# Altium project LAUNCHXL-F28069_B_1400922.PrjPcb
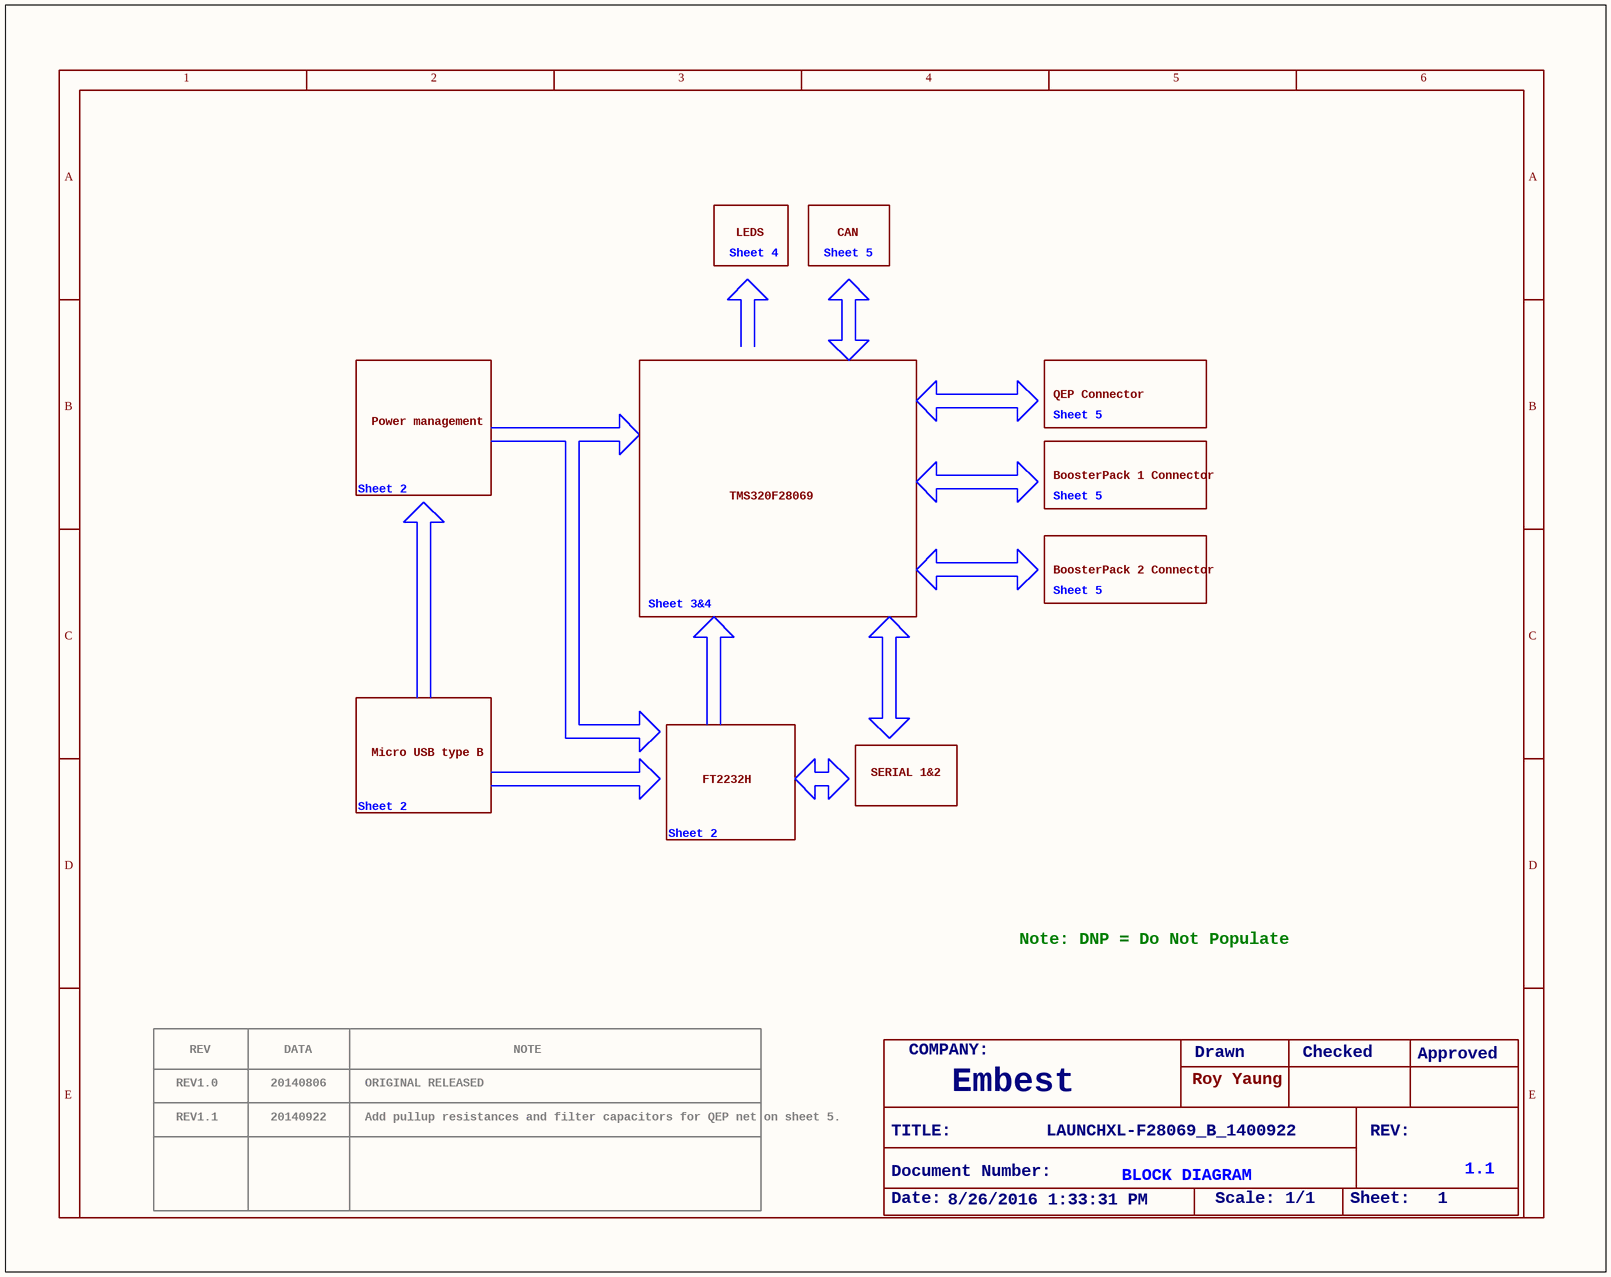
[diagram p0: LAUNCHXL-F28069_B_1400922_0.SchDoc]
7 sheets, 199 parts. Net scope: global (net labels, ports and power ports of the same name join across sheets).
Board file: LAUNCHXL-F28069_B_1400922.PcbDoc
Sheets:
  LAUNCHXL-F28069_B_1400922_0.SchDoc
  LAUNCHXL-F28069_B_1400922_1.SchDoc
  LAUNCHXL-F28069_B_1400922_2.SchDoc
  LAUNCHXL-F28069_B_1400922_3.SchDoc
  LAUNCHXL-F28069_B_1400922_4.SchDoc
  LAUNCHXL-F28069_B_1400922_5.SchDoc
  LAUNCHXL-F28069_B_1400922_6.SchDoc

## Sheet LAUNCHXL-F28069_B_1400922_0.SchDoc: LAUNCHXL-F28069_B_1400922
size 301 x 238 mm; Date: 8/26/2016 1:33:31 PM; SheetNumber: 1

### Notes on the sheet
- Sheet 4
- LEDS
- Sheet 5
- CAN
- QEP Connector
- Power management
- BoosterPack 1 Connector
- Sheet 2
- TMS320F28069
- Sheet 3&4
- BoosterPack 2 Connector
- Micro USB type B
- FT2232H
- SERIAL 1&2
- Note: DNP = Do Not Populate
- REV1.0
- REV
- 20140806
- DATA
- ORIGINAL RELEASED
- NOTE
- COMPANY:
- Embest
- Roy Yaung
- Drawn
- Checked
- Approved
- REV1.1
- 20140922
- Add pullup resistances and filter capacitors for QEP net on sheet 5.
- TITLE:
- LAUNCHXL-F28069_B_1400922
- REV:
- Date:
- Document Number:
- 8/26/2016 1:33:31 PM
- BLOCK DIAGRAM
- Scale: 1/1
- Sheet:
- 1
- 1.1

## Sheet LAUNCHXL-F28069_B_1400922_1.SchDoc: LAUNCHXL-F28069_B_1400922
size 301 x 237 mm; Date: 8/26/2016 1:33:31 PM; SheetNumber: 2
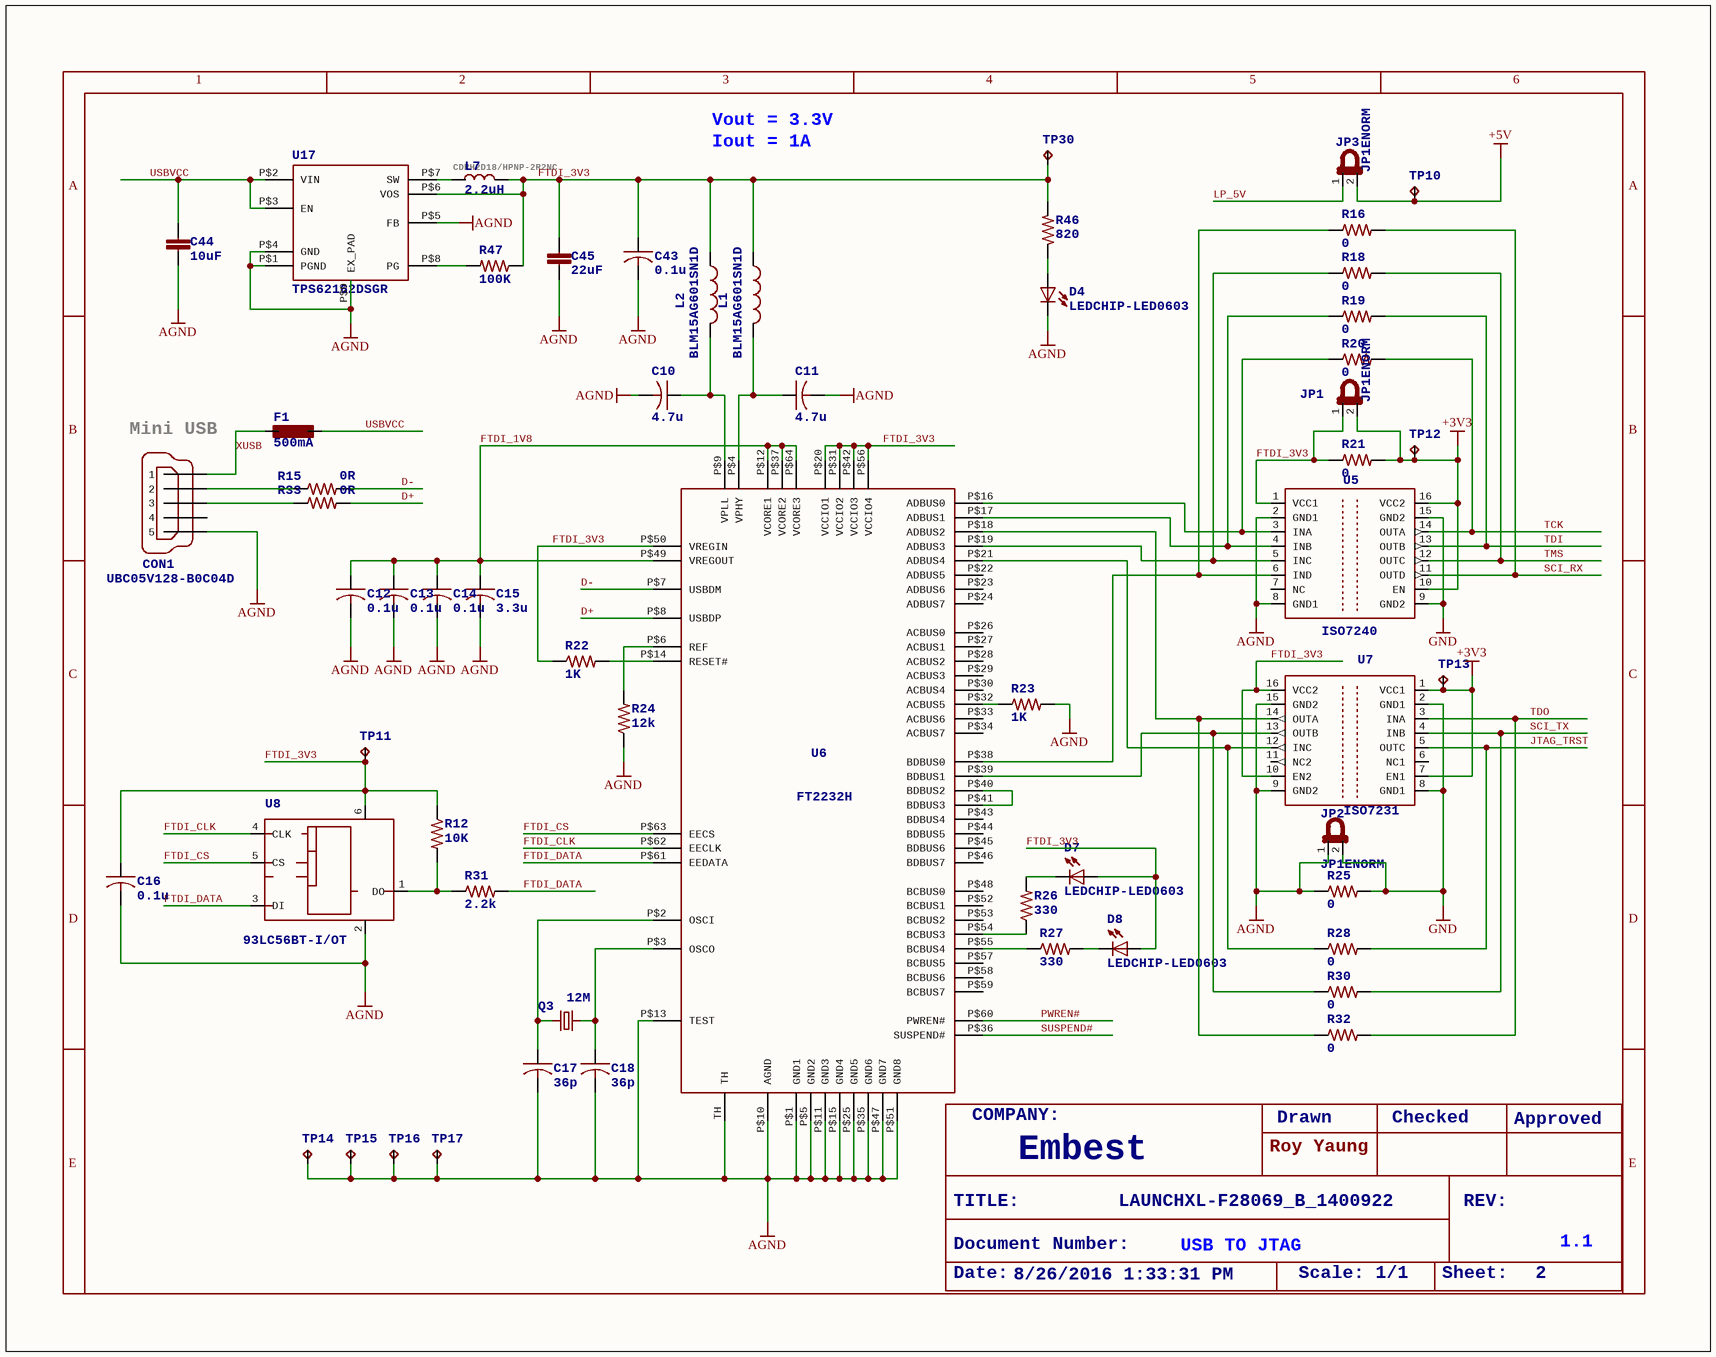
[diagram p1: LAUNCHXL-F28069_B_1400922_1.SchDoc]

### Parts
C10  4.7u  [C0402]
C11  4.7u  [C0402]
C12  0.1u  [C0402]
C13  0.1u  [C0402]
C14  0.1u  [C0402]
C15  3.3u  [C0402]
C16  0.1u  [C0402]
C17  36p  [C0402]
C18  36p  [C0402]
C43  0.1u  [C0402]
C44  10uF  [SPARKFUN_1210]
C45  22uF  [SPARKFUN_1210]
CON1  UBC05V128-B0C04D  [32005-201]
D4  LEDCHIP-LED0603  [CHIP-LED0603]
D7  LEDCHIP-LED0603  [CHIP-LED0603]
D8  LEDCHIP-LED0603  [CHIP-LED0603]
F1  500mA  [L1812]
JP1  JP1ENORM  [JP1]
JP2  JP1ENORM  [JP1]
JP3  JP1ENORM  [JP1]
L1  BLM15AG601SN1D  [R0402]
L2  BLM15AG601SN1D  [R0402]
L7  2.2uH  [INDUCT-3.2*3.2]
Q3  12M  [HC49UP]
R12  10K  [R0402]
R15  0R  [R0402]
R16  0  [R1206]
R18  0  [R1206]
R19  0  [R1206]
R20  0  [R1206]
R21  0  [R1206]
R22  1K  [R0402]
R23  1K  [R0402]
R24  12k  [R0402]
R25  0  [R1206]
R26  330  [R0402]
R27  330  [R0402]
R28  0  [R1206]
R30  0  [R1206]
R31  2.2k  [R0402]
R32  0  [R1206]
R33  0R  [R0402]
R46  820  [R0402]
R47  100K  [R0402]
TP10  TESTPAD_TPB1,27  [TESTPAD_B1,27]  (value not drawn)
TP11  TESTPAD_TPB1,27  [TESTPAD_B1,27]  (value not drawn)
TP12  TESTPAD_TPB1,27  [TESTPAD_B1,27]  (value not drawn)
TP13  TESTPAD_TPB1,27  [TESTPAD_B1,27]  (value not drawn)
TP14  TESTPAD_TPB1,27  [TESTPAD_B1,27]  (value not drawn)
TP15  TESTPAD_TPB1,27  [TESTPAD_B1,27]  (value not drawn)
TP16  TESTPAD_TPB1,27  [TESTPAD_B1,27]  (value not drawn)
TP17  TESTPAD_TPB1,27  [TESTPAD_B1,27]  (value not drawn)
TP30  TESTPAD_TPB1,27  [TESTPAD_B1,27]  (value not drawn)
U5  ISO7240  [SO-16DW]
U6  FT2232H  [QFN64]
U7  ISO7231  [SO-16DW]
U8  93LC56BT-I/OT  [SOT23-6]
U17  TPS62162DSGR  [TI_DSG8]
U$9  ROY_JUMPER  [ROY_JUMPER]  (value not drawn)
U$10  ROY_JUMPER  [ROY_JUMPER]  (value not drawn)
U$11  ROY_JUMPER  [ROY_JUMPER]  (value not drawn)

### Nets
+3V3: JP1.2 R21.2 TP12.TP TP13.TP U5.10(EN) U5.16(VCC2) U7.1(VCC1) U7.7(EN1)
+5V: JP3.2 TP10.TP  [project net EQEP1A]
AGND: C10.2 C11.2 C12.2 C13.2 C14.2 C15.2 C16.2 C17.2 C18.2 C43.2 C44.1 C45.1 CON1.5 D4.C JP2.1 R23.2 R24.1 R25.1 TP14.TP TP15.TP TP16.TP TP17.TP U5.2(GND1) U5.8(GND1) U6.P$1(GND1) U6.P$5(GND2) U6.P$10(AGND) U6.P$11(GND3) U6.P$13(TEST) U6.P$15(GND4) U6.P$25(GND5) U6.P$35(GND6) U6.P$47(GND7) U6.P$51(GND8) U6.TH U7.9(GND2) U7.15(GND2) U8.2(GND) U17.P$1(PGND) U17.P$4(GND) U17.P$5(FB) U17.P$9(EX_PAD)
GND: JP2.2 R25.2 U5.9(GND2) U5.15(GND2) U7.2(GND1) U7.8(GND1)
D+: R33.2 U6.P$8(USBDP)
D-: R15.2 U6.P$7(USBDM)
FTDI_1V8: C12.1 C13.1 C14.1 C15.1 U6.P$12(VCORE1) U6.P$37(VCORE2) U6.P$49(VREGOUT) U6.P$64(VCORE3)
FTDI_3V3: C16.1 C43.1 C45.2 D7.A D8.A JP1.1 L1.1 L2.1 L7.P$1 R12.1 R21.1 R22.1 R46.2 R47.1 TP11.TP TP30.TP U5.1(VCC1) U6.P$20(VCCIO1) U6.P$31(VCCIO2) U6.P$42(VCCIO3) U6.P$50(VREGIN) U6.P$56(VCCIO4) U7.10(EN2) U7.16(VCC2) U8.6(VCC) U17.P$6(VOS)
FTDI_CLK: U6.P$62(EECLK) U8.4(CLK)
FTDI_CS: U6.P$63(EECS) U8.5(CS)
FTDI_DATA: R31.2 U6.P$61(EEDATA) U8.3(DI)
JTAG_TRST: R28.2 U7.5(OUTC)
LP_5V: JP3.1
PWREN#: U6.P$60(PWREN#)
SCI_RX: R16.2 U5.11(OUTD)
SCI_TX: R30.2 U7.4(INB)
SUSPEND#: U6.P$36(SUSPEND#)
TCK: R20.2 U5.14(OUTA)
TDI: R19.2 U5.13(OUTB)
TDO: R32.2 U7.3(INA)
TMS: R18.2 U5.12(OUTC)
USBVCC: C44.2 F1.1 U17.P$2(VIN) U17.P$3(EN)
XUSB: CON1.1 F1.2
NetC10_1: C10.1 L2.2 U6.P$9(VPLL)
NetC11_1: C11.1 L1.2 U6.P$4(VPHY)
NetC17_1: C17.1 Q3.1 U6.P$2(OSCI)
NetC18_1: C18.1 Q3.2 U6.P$3(OSCO)
NetCON1_2: CON1.2 R15.1
NetCON1_3: CON1.3 R33.1
NetD4_A: D4.A R46.1
NetD7_C: D7.C R26.2
NetD8_C: D8.C R27.2
NetL7_P$2: L7.P$2 U17.P$7(SW)
NetR12_2: R12.2 R31.1 U8.1(DO)
NetR16_1: R16.1 U5.6(IND) U6.P$38(BDBUS0)
NetR18_1: R18.1 U5.5(INC) U6.P$19(ADBUS3)
NetR19_1: R19.1 U5.4(INB) U6.P$17(ADBUS1)
NetR20_1: R20.1 U5.3(INA) U6.P$16(ADBUS0)
NetR22_2: R22.2 U6.P$14(RESET#)
NetR23_1: R23.1 U6.P$32(ACBUS5)
NetR24_2: R24.2 U6.P$6(REF)
NetR26_1: R26.1 U6.P$54(BCBUS3)
NetR27_1: R27.1 U6.P$55(BCBUS4)
NetR28_1: R28.1 U6.P$21(ADBUS4) U7.12(INC)
NetR30_1: R30.1 U6.P$39(BDBUS1) U7.13(OUTB)
NetR32_1: R32.1 U6.P$18(ADBUS2) U7.14(OUTA)
NetR47_2: R47.2 U17.P$8(PG)
NetU6_P$40: U6.P$40(BDBUS2) U6.P$41(BDBUS3)

Not connected (* = marked no-connect by the designer): CON1 4; U5 7(NC); U6 P$22(ADBUS5) P$23(ADBUS6) P$24(ADBUS7) P$26(ACBUS0) P$27(ACBUS1) P$28(ACBUS2) P$29(ACBUS3) P$30(ACBUS4) P$33(ACBUS6) P$34(ACBUS7) P$43(BDBUS4) P$44(BDBUS5) P$45(BDBUS6) P$46(BDBUS7) P$48(BCBUS0) P$52(BCBUS1) P$53(BCBUS2) P$57(BCBUS5) P$58(BCBUS6) P$59(BCBUS7); U7 6(NC1) 11(NC2)

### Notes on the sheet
- Vout = 3.3V
- Iout = 1A
- (near L7) CDRH2D18/HPNP-2R2NC
- (near CON1) Mini USB
- (near U6) COMPANY:
- Embest
- Roy Yaung
- Drawn
- Checked
- Approved
- TITLE:
- LAUNCHXL-F28069_B_1400922
- REV:
- Date:
- Document Number:
- 8/26/2016 1:33:31 PM
- USB TO JTAG
- Scale: 1/1
- Sheet:
- 2
- 1.1

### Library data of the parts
C10-C18 C43 = C-USC0402: CAPACITOR, American symbol
C44 C45 = SPARKFUN_CAP1210: CapacitorStandard 0603 ceramic capacitor, and 0.1" leaded capacitor.
CON1 = MINI-USB-32005-201: MINI USB-B Conector   Source: www.cypressindustries.com
D4 D7 D8 = LEDCHIP-LED0603: LED   OSRAM: - CHIPLED LG R971, LG N971, LY N971, LG Q971, LY Q971, LO R971, LY R971 LH N974, LH R974 LS Q976, LO Q976, LY Q976 LO Q996 - Hyper CHIPLED LW Q18S LB Q993, LB Q99A, LB R99A - SideLED LS A670, LO A670, LY A670, LG A670, LP A670 LB A673, LV A673, LT A673, LW A673 LH A674 LY A675 LS A676, LA A676, LO A676, LY A676, LW A676 LS A679, LY A679, LG A679 -  Hyper Micro SIDELED® LS Y876, LA Y876, LO Y876, LY Y876 LT Y87S - SmartLED LW L88C, LW L88S LB L89C, LB L89S, LG L890 LS L89K, LO L89K, LY L89K LS L896, LA L896, LO L896, LY L896 - TOPLED LS T670, LO T670, LY T670, LG T670, LP T670 LSG T670, LSP T670, LSY T670, LOP T670, LYG T670 LG T671, LOG T671, LSG T671 LB T673, LV T673, LT T673, LW T673 LH T674 LS T676, LA T676, LO T676, LY T676, LB T676, LH T676, LSB T676, LW T676 LB T67C, LV T67C, LT T67C, LS T67K, LO T67K, LY T67K, LW E67C LS E67B, LA E67B, LO E67B, LY E67B, LB E67C, LV E67C, LT E67C LW T67C LS T679, LY T679, LG T679 LS T770, LO T770, LY T770, LG T770, LP T770 LB T773, LV T773, LT T773, LW T773 LH T774 LS E675, LA E675, LY E675, LS T675 LS T776, LA T776, LO T776, LY T776, LB T776 LHGB T686 LT T68C, LB T68C - Hyper Mini TOPLED® LB M676 - Mini TOPLED Santana® LG M470 LS M47K, LO M47K, LY M47K    Source: http://www.osram.convergy.de   LUXEON: - LUMILED® LXK2-PW12-R00, LXK2-PW12-S00, LXK2-PW14-U00, LXK2-PW14-V00 LXK2-PM12-R00, LXK2-PM12-S00, LXK2-PM14-U00 LXK2-PE12-Q00, LXK2-PE12-R00, LXK2-PE12-S00, LXK2-PE14-T00, LXK2-PE14-U00 LXK2-PB12-K00, LXK2-PB12-L00, LXK2-PB12-M00, LXK2-PB14-N00, LXK2-PB14-P00, LXK2-PB14-Q00 LXK2-PR12-L00, LXK2-PR12-M00, LXK2-PR14-Q00, LXK2-PR14-R00 LXK2-PD12-Q00, LXK2-PD12-R00, LXK2-PD12-S00 LXK2-PH12-R00, LXK2-PH12-S00 LXK2-PL12-P00, LXK2-PL12-Q00, LXK2-PL12-R00    Source: www.luxeon.com   KINGBRIGHT:   KA-3528ASYC Source: www.kingbright.com
F1 = L-EUL1812: INDUCTOR, European symbol
JP1-JP3 = JP1ENORM: JUMPER
L1 L2 = L-US0402: INDUCTOR, American symbol
L7 = VLF4012A`
Q3 = CRYSTALHC49UP: CRYSTAL
R12 R15 R22-R24 R26 R27 R31 R33 R46 R47 = R-US_R0402: RESISTOR, American symbol
R16 R18-R21 R25 R28 R30 R32 = R-US_R1206: RESISTOR, American symbol
TP10-TP17 TP30 = TESTPAD_TPB1,27: Test pad
U5 = ISO7240: HIGH SPEED QUAD DIGITAL ISOLATORS   Source: http://focus.ti.com/lit/ds/symlink/iso7240m.pdf
U8 = 93*: Serial EPROM   1 K/2 K/4 K, low voltage, Microwire

## Sheet LAUNCHXL-F28069_B_1400922_2.SchDoc: LAUNCHXL-F28069_B_1400922
size 301 x 237 mm; Date: 8/26/2016 1:33:33 PM; SheetNumber: 3
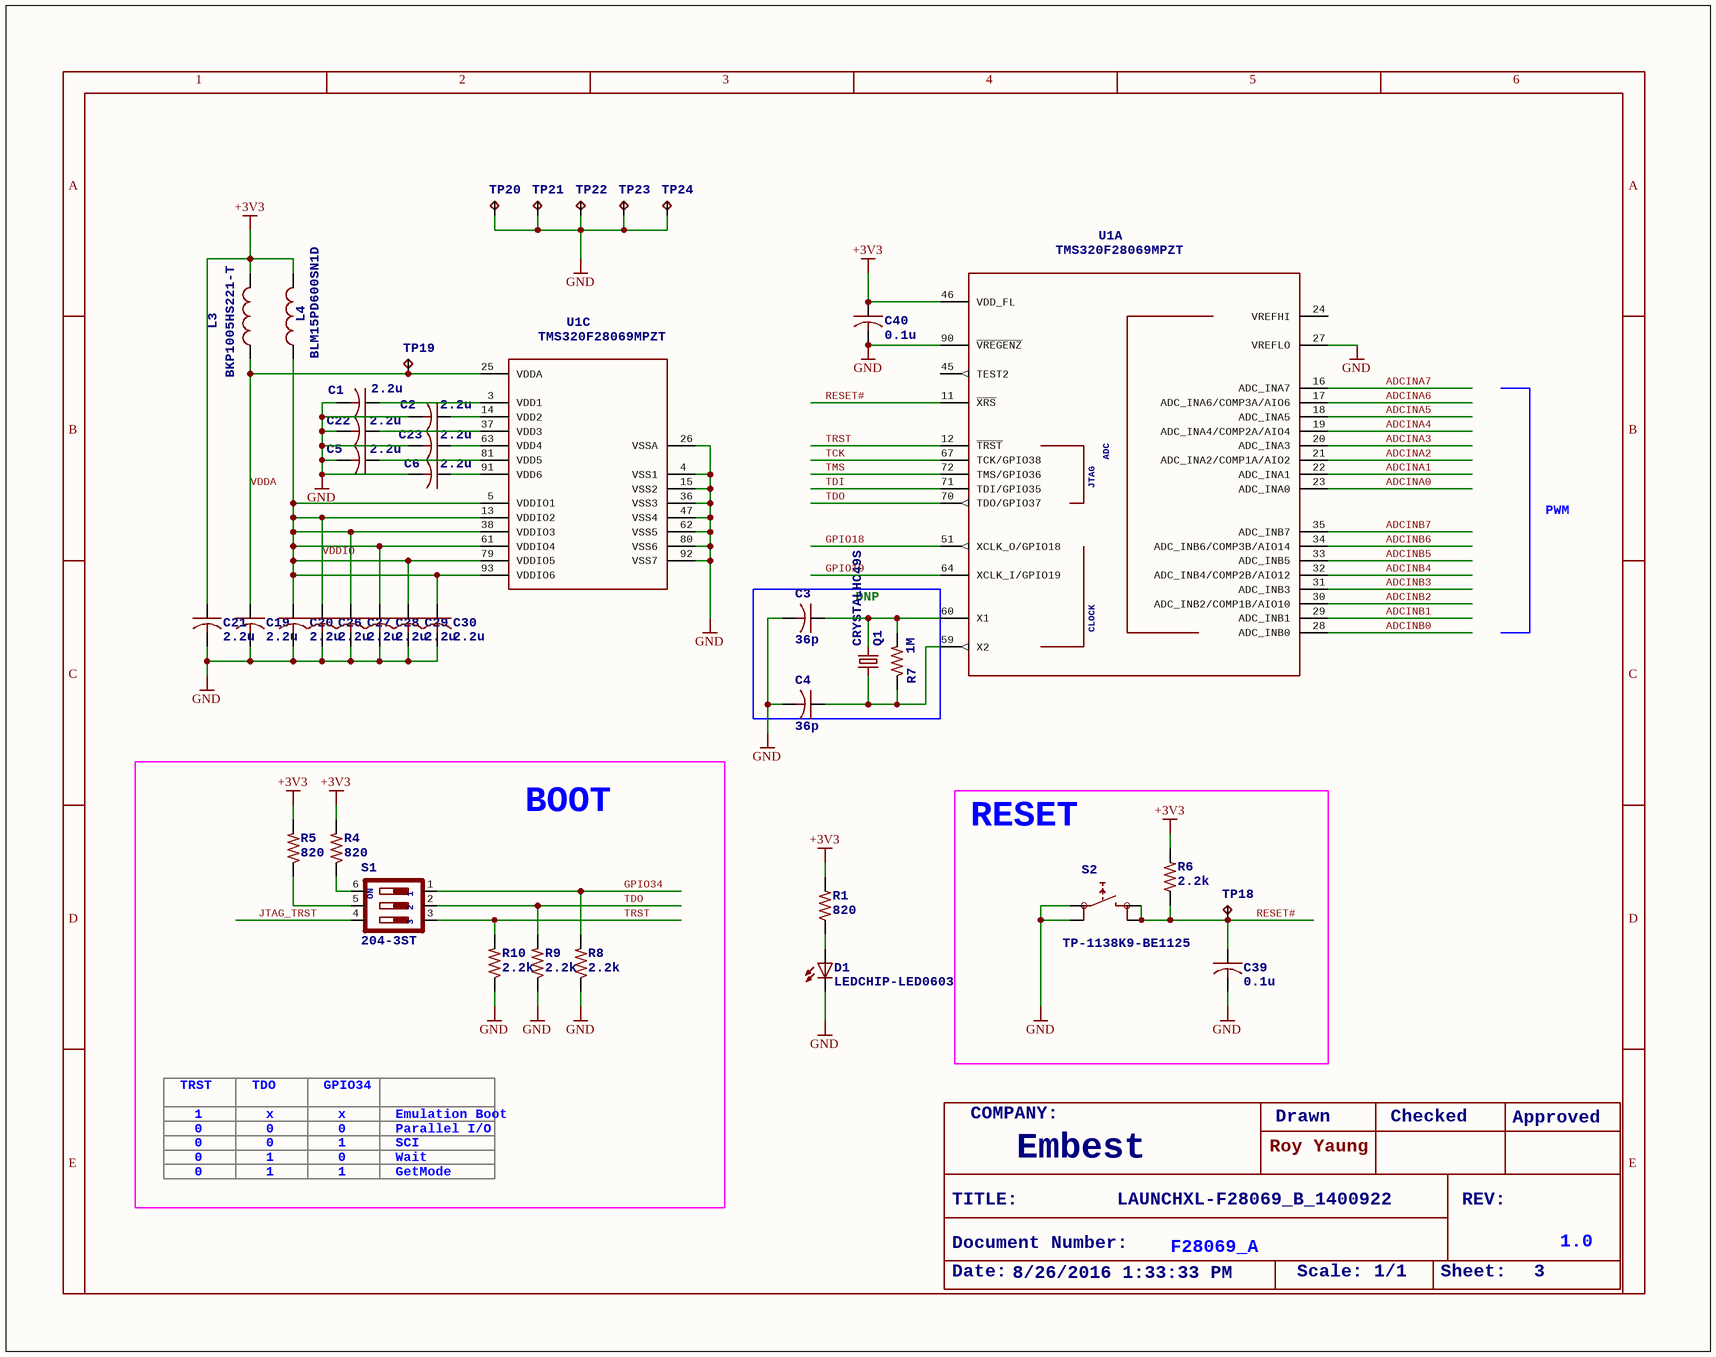
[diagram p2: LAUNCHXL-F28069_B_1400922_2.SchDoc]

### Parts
C1  2.2u  [C0402]
C2  2.2u  [C0402]
C3  36p  [C0402]
C4  36p  [C0402]
C5  2.2u  [C0402]
C6  2.2u  [C0402]
C19  2.2u  [C0402]
C20  2.2u  [C0402]
C21  2.2u  [C0402]
C22  2.2u  [C0402]
C23  2.2u  [C0402]
C26  2.2u  [C0402]
C27  2.2u  [C0402]
C28  2.2u  [C0402]
C29  2.2u  [C0402]
C30  2.2u  [C0402]
C39  0.1u  [C0402]
C40  0.1u  [C0402]
D1  LEDCHIP-LED0603  [CHIP-LED0603]
L3  BKP1005HS221-T  [R0402]
L4  BLM15PD600SN1D  [R0402]
Q1  CRYSTALHC49S  [HC49/S]
R1  820  [R0402]
R4  820  [R0402]
R5  820  [R0402]
R6  2.2k  [R0402]
R7  1M  [R0402]
R8  2.2k  [R0402]
R9  2.2k  [R0402]
R10  2.2k  [R0402]
S1  204-3ST  [CTS-219-03]
S2  TP-1138K9-BE1125  [FSMJSMA]
TP18  TESTPAD_TPB1,27  [TESTPAD_B1,27]  (value not drawn)
TP19  TESTPAD_TPB1,27  [TESTPAD_B1,27]  (value not drawn)
TP20  TESTPAD_TPB1,27  [TESTPAD_B1,27]  (value not drawn)
TP21  TESTPAD_TPB1,27  [TESTPAD_B1,27]  (value not drawn)
TP22  TESTPAD_TPB1,27  [TESTPAD_B1,27]  (value not drawn)
TP23  TESTPAD_TPB1,27  [TESTPAD_B1,27]  (value not drawn)
TP24  TESTPAD_TPB1,27  [TESTPAD_B1,27]  (value not drawn)
U1  TMS320F28069MPZT  [PQFP100]  (parts A,C of 3)

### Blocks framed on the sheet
DNP: C3 C4 Q1 R7
BOOT: R4 R5 R8-R10 S1
RESET: C39 R6 S2 TP18

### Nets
+3V3: C21.1 C40.1 L3.2 L4.2 R1.2 R4.2 R5.2 R6.2 U1.46(VDD_FL)
GND: C1.2 C2.2 C3.2 C4.2 C5.2 C6.2 C19.2 C20.2 C21.2 C22.2 C23.2 C26.2 C27.2 C28.2 C29.2 C30.2 C39.2 C40.2 D1.C R8.1 R9.1 R10.1 S2.P$1 S2.P$2 TP20.TP TP21.TP TP22.TP TP23.TP TP24.TP U1.4(VSS1) U1.15(VSS2) U1.26(VSSA) U1.27(VREFLO) U1.36(VSS3) U1.47(VSS4) U1.62(VSS5) U1.80(VSS6) U1.90(~{VREGENZ}) U1.92(VSS7)
ADCINA0: U1.23(ADC_INA0)
ADCINA1: U1.22(ADC_INA1)
ADCINA2: U1.21(ADC_INA2/COMP1A/AIO2)
ADCINA3: U1.20(ADC_INA3)
ADCINA4: U1.19(ADC_INA4/COMP2A/AIO4)
ADCINA5: U1.18(ADC_INA5)
ADCINA6: U1.17(ADC_INA6/COMP3A/AIO6)
ADCINA7: U1.16(ADC_INA7)
ADCINB0: U1.28(ADC_INB0)
ADCINB1: U1.29(ADC_INB1)
ADCINB2: U1.30(ADC_INB2/COMP1B/AIO10)
ADCINB3: U1.31(ADC_INB3)
ADCINB4: U1.32(ADC_INB4/COMP2B/AIO12)
ADCINB5: U1.33(ADC_INB5)
ADCINB6: U1.34(ADC_INB6/COMP3B/AIO14)
ADCINB7: U1.35(ADC_INB7)
GPIO18: U1.51(XCLK_O/GPIO18)
GPIO19: U1.64(XCLK_I/GPIO19)
GPIO34: R8.2 S1.1
JTAG_TRST: S1.4
RESET#: C39.1 R6.1 S2.P$3 S2.P$4 TP18.TP U1.11(~{XRS})
TCK: U1.67(TCK/GPIO38)
TDI: U1.71(TDI/GPIO35)
TDO: R9.2 S1.2 U1.70(TDO/GPIO37)
TMS: U1.72(TMS/GPIO36)
TRST: R10.2 S1.3 U1.12(~{TRST})
VDDA: C19.1 L3.1 TP19.TP U1.25(VDDA)
VDDIO: C20.1 C26.1 C27.1 C28.1 C29.1 C30.1 L4.1 U1.5(VDDIO1) U1.13(VDDIO2) U1.38(VDDIO3) U1.61(VDDIO4) U1.79(VDDIO5) U1.93(VDDIO6)
NetC1_1: C1.1 U1.3(VDD1)
NetC2_1: C2.1 U1.14(VDD2)
NetC3_1: C3.1 Q1.2 R7.2 U1.60(X1)
NetC4_1: C4.1 Q1.1 R7.1 U1.59(X2)
NetC5_1: C5.1 U1.81(VDD5)
NetC6_1: C6.1 U1.91(VDD6)
NetC22_1: C22.1 U1.37(VDD3)
NetC23_1: C23.1 U1.63(VDD4)
NetD1_A: D1.A R1.1
NetR4_1: R4.1 S1.6
NetR5_1: R5.1 S1.5

Not connected (* = marked no-connect by the designer): U1 24(VREFHI) 45(TEST2)

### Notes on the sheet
- PWM
- TRST
- TDO
- GPIO34
- 1
- 0
- x
- Emulation Boot
- Parallel I/O
- SCI
- Wait
- COMPANY:
- Embest
- Roy Yaung
- Drawn
- Checked
- Approved
- GetMode
- TITLE:
- LAUNCHXL-F28069_B_1400922
- REV:
- Date:
- Document Number:
- 8/26/2016 1:33:33 PM
- F28069_A
- Scale: 1/1
- Sheet:
- 3
- 1.0

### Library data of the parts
C1-C6 C19-C23 C26-C30 C39 C40 = C-USC0402: CAPACITOR, American symbol
D1 = LEDCHIP-LED0603: as D4 on sheet LAUNCHXL-F28069_B_1400922_1
L3 L4 = L-US0402: INDUCTOR, American symbol
Q1 = CRYSTALHC49S: CRYSTAL
R1 R4-R10 = R-US_R0402: RESISTOR, American symbol
S1 = 219-03*: Surface Mount DIP Switch Series 219 SMT   CTS Electronic Components Sourc: www.ctscorp.com
S2 = FSMJSMA
TP18-TP24 = TESTPAD_TPB1,27: Test pad
U1 = TMS320F28069PZSR

## Sheet LAUNCHXL-F28069_B_1400922_3.SchDoc: LAUNCHXL-F28069_B_1400922
size 301 x 237 mm; Date: 8/26/2016 1:33:34 PM; SheetNumber: 4
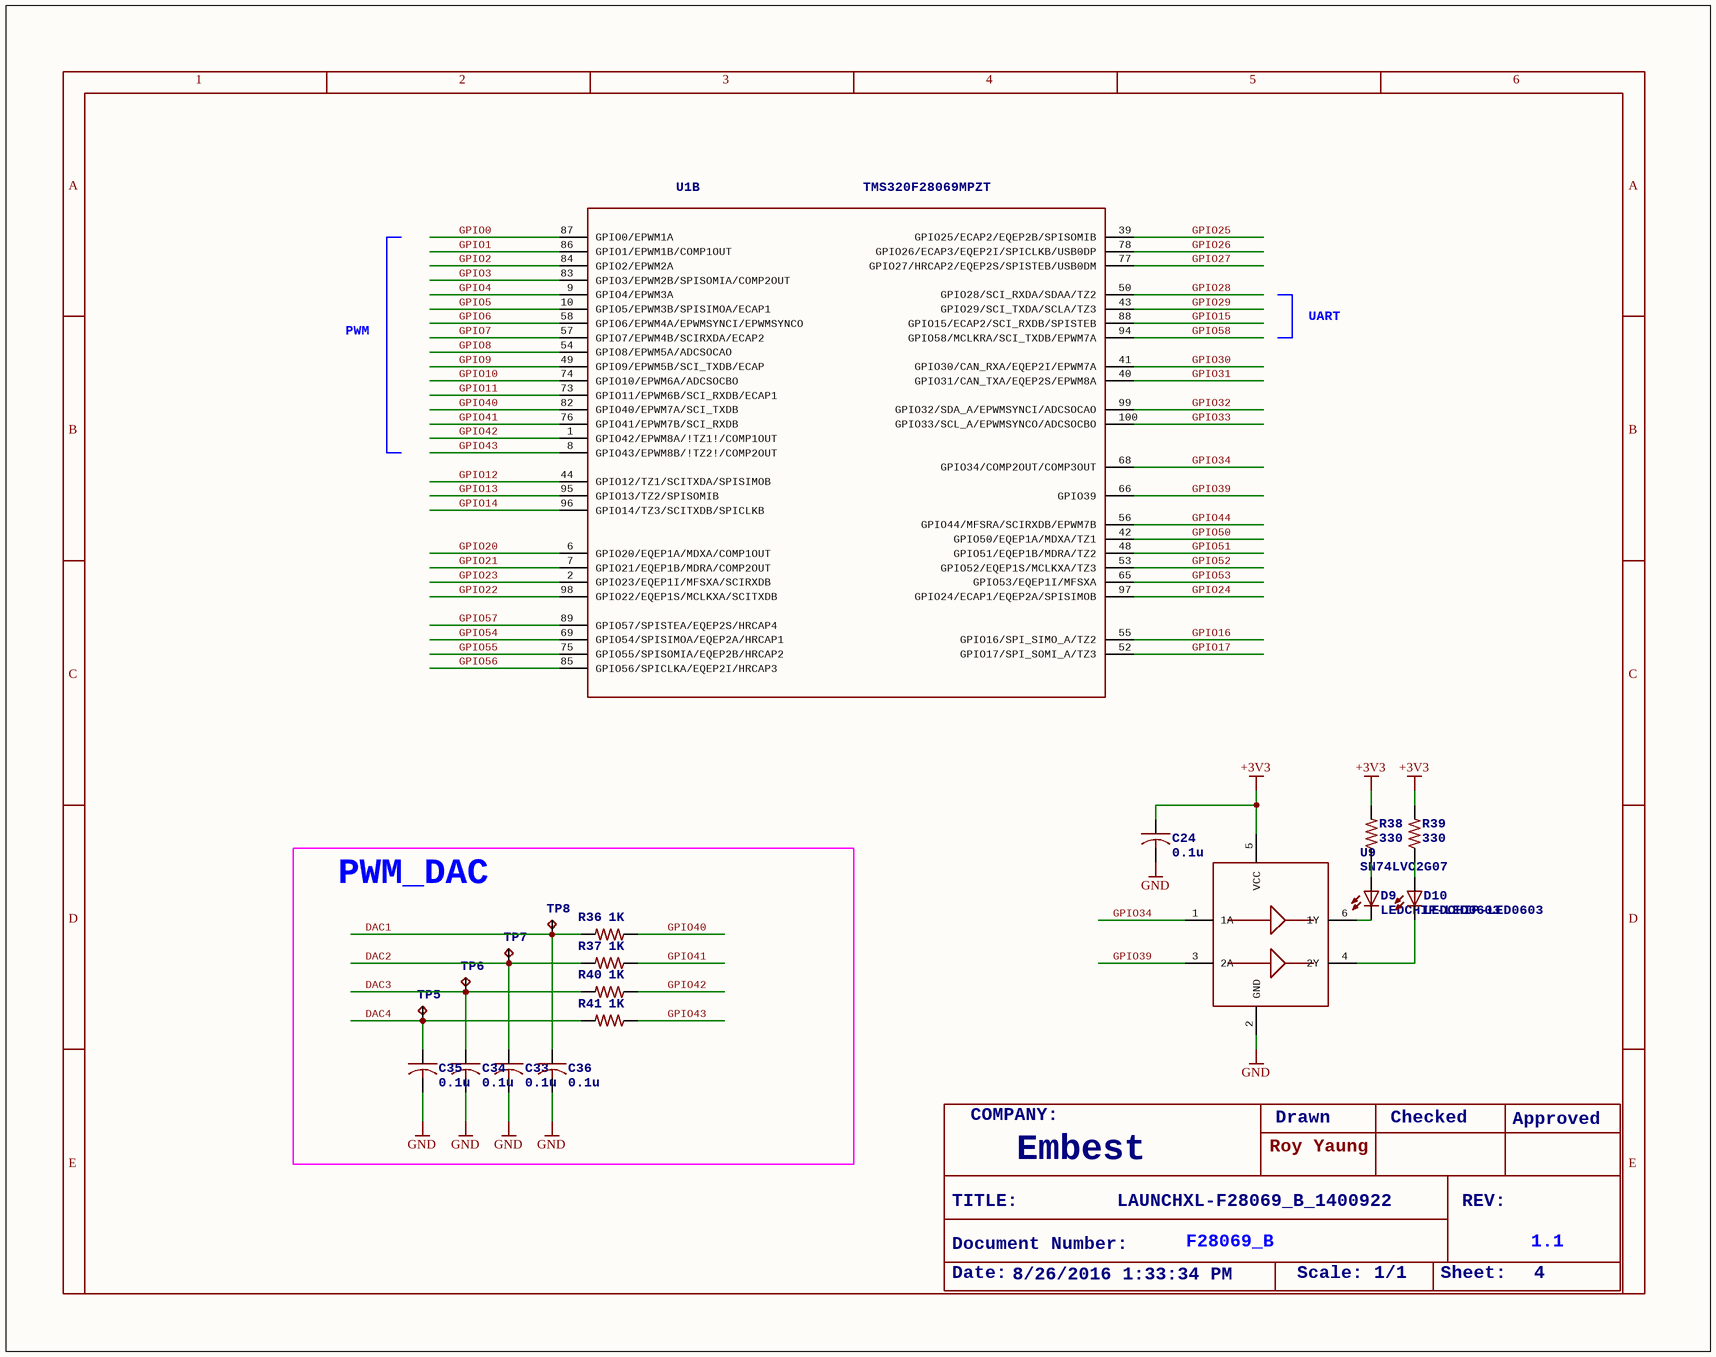
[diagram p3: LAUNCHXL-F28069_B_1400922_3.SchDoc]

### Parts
C24  0.1u  [C0402]
C33  0.1u  [C0402]
C34  0.1u  [C0402]
C35  0.1u  [C0402]
C36  0.1u  [C0402]
D9  LEDCHIP-LED0603  [CHIP-LED0603]
D10  LEDCHIP-LED0603  [CHIP-LED0603]
R36  1K  [R0402]
R37  1K  [R0402]
R38  330  [R0402]
R39  330  [R0402]
R40  1K  [R0402]
R41  1K  [R0402]
TP5  TESTPAD_TPB1,27  [TESTPAD_B1,27]  (value not drawn)
TP6  TESTPAD_TPB1,27  [TESTPAD_B1,27]  (value not drawn)
TP7  TESTPAD_TPB1,27  [TESTPAD_B1,27]  (value not drawn)
TP8  TESTPAD_TPB1,27  [TESTPAD_B1,27]  (value not drawn)
U1  TMS320F28069MPZT  [PQFP100]  (part B of 3)
U9  SN74LVC2G07  [SOT23-6-DBV]

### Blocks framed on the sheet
PWM_DAC: C33-C36 R36 R37 R40 R41 TP5-TP8

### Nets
+3V3: C24.1 R38.2 R39.2 U9.5(VCC)
GND: C24.2 C33.2 C34.2 C35.2 C36.2 U9.2(GND)
DAC1: C36.1 R36.2 TP8.TP
DAC2: C33.1 R37.2 TP7.TP
DAC3: C34.1 R40.2 TP6.TP
DAC4: C35.1 R41.2 TP5.TP
GPIO0: U1.87(GPIO0/EPWM1A)
GPIO1: U1.86(GPIO1/EPWM1B/COMP1OUT)
GPIO2: U1.84(GPIO2/EPWM2A)
GPIO3: U1.83(GPIO3/EPWM2B/SPISOMIA/COMP2OUT)
GPIO4: U1.9(GPIO4/EPWM3A)
GPIO5: U1.10(GPIO5/EPWM3B/SPISIMOA/ECAP1)
GPIO6: U1.58(GPIO6/EPWM4A/EPWMSYNCI/EPWMSYNCO)
GPIO7: U1.57(GPIO7/EPWM4B/SCIRXDA/ECAP2)
GPIO8: U1.54(GPIO8/EPWM5A/ADCSOCAO)
GPIO9: U1.49(GPIO9/EPWM5B/SCI_TXDB/ECAP)
GPIO10: U1.74(GPIO10/EPWM6A/ADCSOCBO)
GPIO11: U1.73(GPIO11/EPWM6B/SCI_RXDB/ECAP1)
GPIO12: U1.44(GPIO12/TZ1/SCITXDA/SPISIMOB)
GPIO13: U1.95(GPIO13/TZ2/SPISOMIB)
GPIO14: U1.96(GPIO14/TZ3/SCITXDB/SPICLKB)
GPIO15: U1.88(GPIO15/ECAP2/SCI_RXDB/SPISTEB)
GPIO16: U1.55(GPIO16/SPI_SIMO_A/TZ2)
GPIO17: U1.52(GPIO17/SPI_SOMI_A/TZ3)
GPIO20: U1.6(GPIO20/EQEP1A/MDXA/COMP1OUT)
GPIO21: U1.7(GPIO21/EQEP1B/MDRA/COMP2OUT)
GPIO22: U1.98(GPIO22/EQEP1S/MCLKXA/SCITXDB)
GPIO23: U1.2(GPIO23/EQEP1I/MFSXA/SCIRXDB)
GPIO24: U1.97(GPIO24/ECAP1/EQEP2A/SPISIMOB)
GPIO25: U1.39(GPIO25/ECAP2/EQEP2B/SPISOMIB)
GPIO26: U1.78(GPIO26/ECAP3/EQEP2I/SPICLKB/USB0DP)
GPIO27: U1.77(GPIO27/HRCAP2/EQEP2S/SPISTEB/USB0DM)
GPIO28: U1.50(GPIO28/SCI_RXDA/SDAA/TZ2)
GPIO29: U1.43(GPIO29/SCI_TXDA/SCLA/TZ3)
GPIO30: U1.41(GPIO30/CAN_RXA/EQEP2I/EPWM7A)
GPIO31: U1.40(GPIO31/CAN_TXA/EQEP2S/EPWM8A)
GPIO32: U1.99(GPIO32/SDA_A/EPWMSYNCI/ADCSOCAO)
GPIO33: U1.100(GPIO33/SCL_A/EPWMSYNCO/ADCSOCBO)
GPIO34: U1.68(GPIO34/COMP2OUT/COMP3OUT) U9.1(1A)
GPIO39: U1.66(GPIO39) U9.3(2A)
GPIO40: R36.1 U1.82(GPIO40/EPWM7A/SCI_TXDB)
GPIO41: R37.1 U1.76(GPIO41/EPWM7B/SCI_RXDB)
GPIO42: R40.1 U1.1(GPIO42/EPWM8A/!TZ1!/COMP1OUT)
GPIO43: R41.1 U1.8(GPIO43/EPWM8B/!TZ2!/COMP2OUT)
GPIO44: U1.56(GPIO44/MFSRA/SCIRXDB/EPWM7B)
GPIO50: U1.42(GPIO50/EQEP1A/MDXA/TZ1)
GPIO51: U1.48(GPIO51/EQEP1B/MDRA/TZ2)
GPIO52: U1.53(GPIO52/EQEP1S/MCLKXA/TZ3)
GPIO53: U1.65(GPIO53/EQEP1I/MFSXA)
GPIO54: U1.69(GPIO54/SPISIMOA/EQEP2A/HRCAP1)
GPIO55: U1.75(GPIO55/SPISOMIA/EQEP2B/HRCAP2)
GPIO56: U1.85(GPIO56/SPICLKA/EQEP2I/HRCAP3)
GPIO57: U1.89(GPIO57/SPISTEA/EQEP2S/HRCAP4)
GPIO58: U1.94(GPIO58/MCLKRA/SCI_TXDB/EPWM7A)
NetD9_A: D9.A R38.1
NetD9_C: D9.C U9.6(1Y)
NetD10_A: D10.A R39.1
NetD10_C: D10.C U9.4(2Y)

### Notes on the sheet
- PWM
- UART
- COMPANY:
- Embest
- Roy Yaung
- Drawn
- Checked
- Approved
- TITLE:
- LAUNCHXL-F28069_B_1400922
- REV:
- Date:
- Document Number:
- 8/26/2016 1:33:34 PM
- F28069_B
- Scale: 1/1
- Sheet:
- 1.1
- 4

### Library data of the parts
C24 C33-C36 = C-USC0402: CAPACITOR, American symbol
D9 D10 = LEDCHIP-LED0603: as D4 on sheet LAUNCHXL-F28069_B_1400922_1
R36-R41 = R-US_R0402: RESISTOR, American symbol
TP5-TP8 = TESTPAD_TPB1,27: Test pad
U1 = TMS320F28069PZSR

## Sheet LAUNCHXL-F28069_B_1400922_4.SchDoc: LAUNCHXL-F28069_B_1400922
size 301 x 237 mm; Date: 8/26/2016 1:33:35 PM; SheetNumber: 5
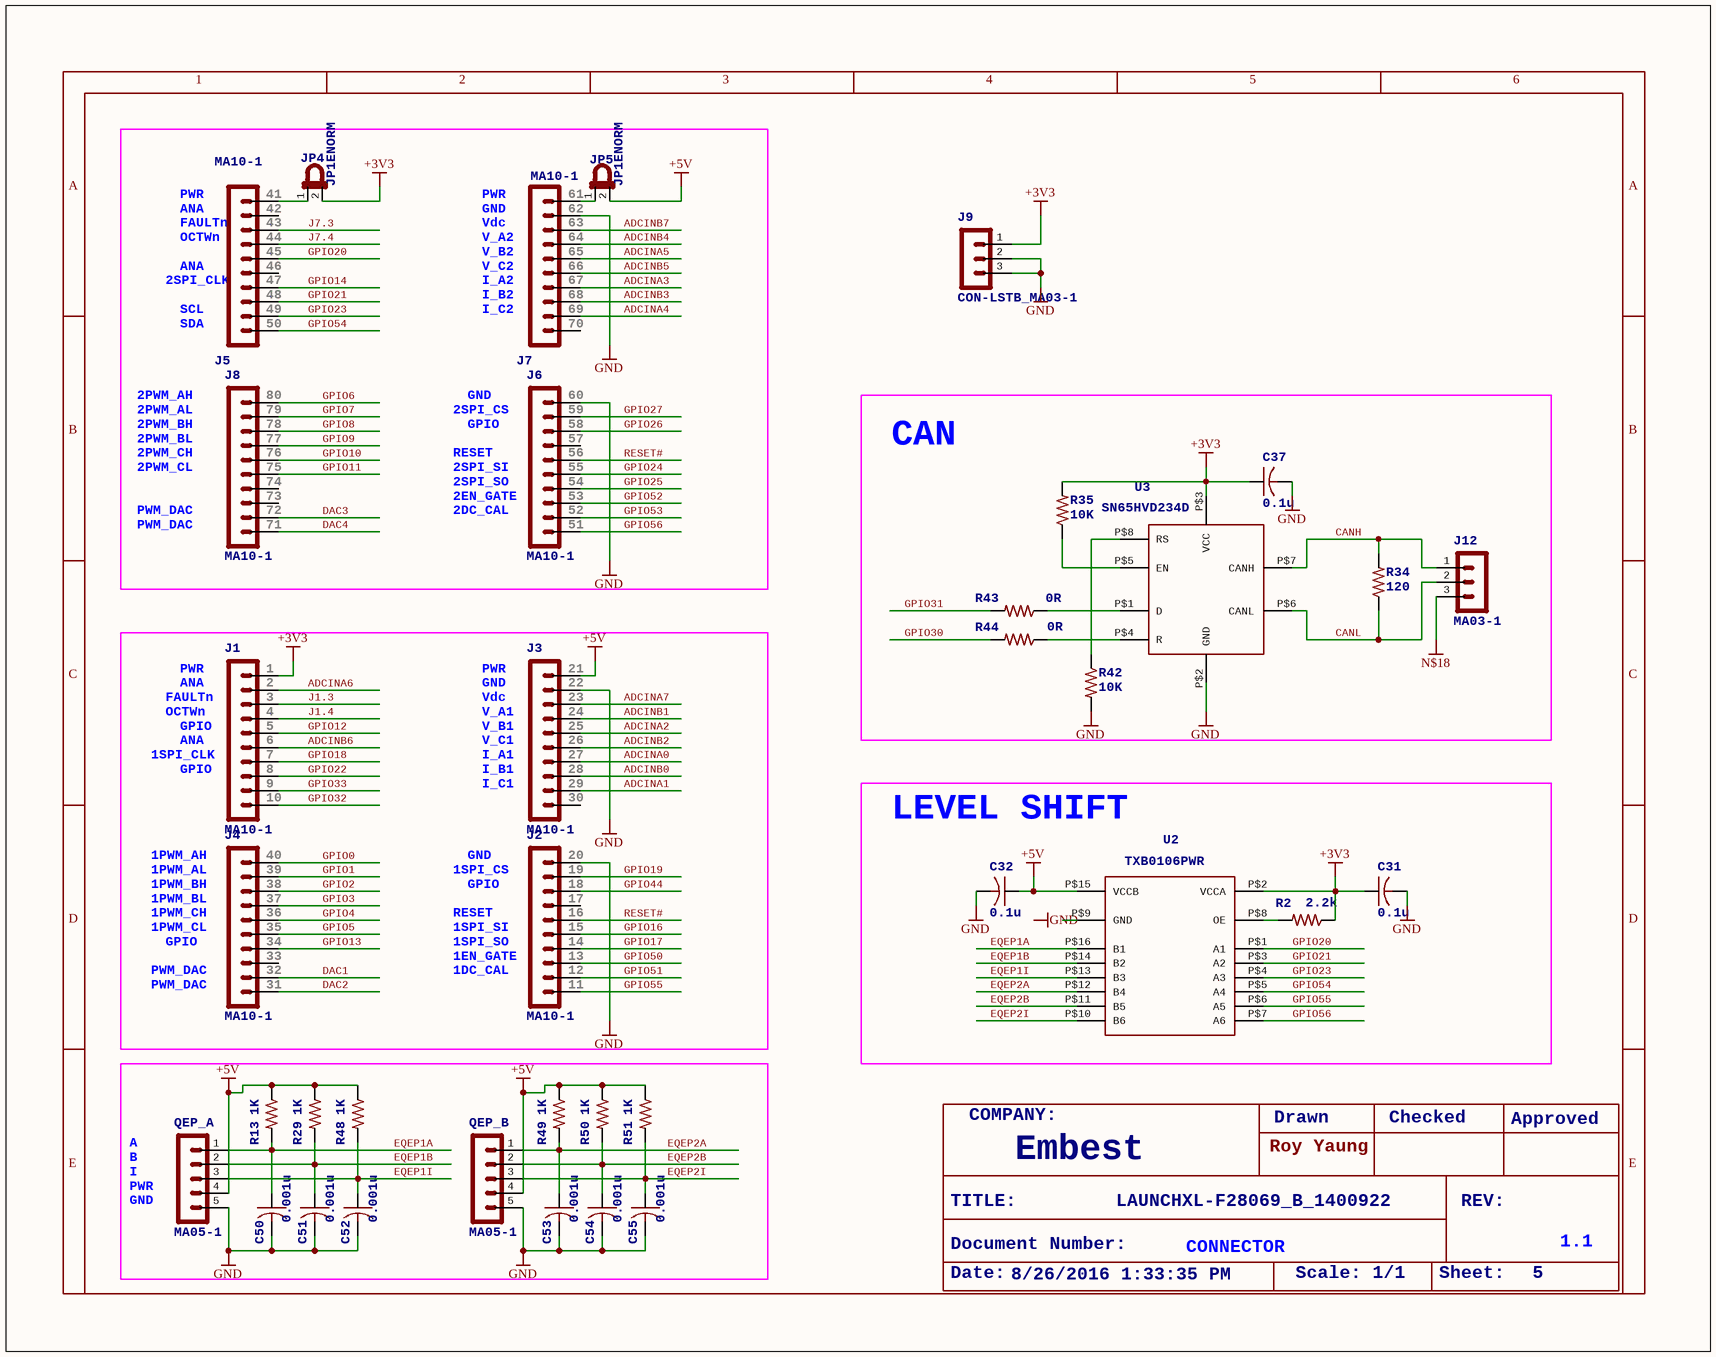
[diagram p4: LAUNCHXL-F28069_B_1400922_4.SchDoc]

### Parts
C31  0.1u  [C0402]
C32  0.1u  [C0402]
C37  0.1u  [C0402]
C50  0.001u  [C0402]
C51  0.001u  [C0402]
C52  0.001u  [C0402]
C53  0.001u  [C0402]
C54  0.001u  [C0402]
C55  0.001u  [C0402]
J1  MA10-1  [MA10-1]
J2  MA10-1  [MA10-1]
J3  MA10-1  [MA10-1]
J4  MA10-1  [MA10-1]
J5  MA10-1  [MA10-1]
J6  MA10-1  [MA10-1]
J7  MA10-1  [MA10-1]
J8  MA10-1  [MA10-1]
J9  CON-LSTB_MA03-1  [CON-LSTB_MA03-1]
J12  MA03-1  [MA03-1]
JP4  JP1ENORM  [JP1]
JP5  JP1ENORM  [JP1]
QEP_A  MA05-1  [MA05-1]
QEP_B  MA05-1  [MA05-1]
R2  2.2k  [R0402]
R13  1K  [R0402]
R29  1K  [R0402]
R34  120  [R0402]
R35  10K  [R0402]
R42  10K  [R0402]
R43  0R  [R0402]
R44  0R  [R0402]
R48  1K  [R0402]
R49  1K  [R0402]
R50  1K  [R0402]
R51  1K  [R0402]
U2  TXB0106PWR  [TSSOP16-PW]
U3  SN65HVD234D  [SOIC8-PDSO]
U$12  ROY_JUMPER  [ROY_JUMPER]  (value not drawn)
U$13  ROY_JUMPER  [ROY_JUMPER]  (value not drawn)

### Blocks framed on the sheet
CAN: C37 J12 R34 R35 R42-R44 U3
LEVEL SHIFT: C31 C32 R2 U2

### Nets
+3V3: C31.1 C37.1 J1.1 J9.1 JP4.2 R2.1 R35.2 U2.P$2(VCCA) U3.P$3(VCC)
EQEP1A: C32.1 C50.1 C51.1 C52.1 C53.1 C54.1 C55.1 J3.1 JP5.2 QEP_A.1 QEP_A.2 QEP_A.3 QEP_A.4 QEP_B.1 QEP_B.2 QEP_B.3 QEP_B.4 R13.1 R13.2 R29.1 R29.2 R48.1 R48.2 R49.1 R49.2 R50.1 R50.2 R51.1 R51.2 U2.P$10(B6) U2.P$11(B5) U2.P$12(B4) U2.P$13(B3) U2.P$14(B2) U2.P$15(VCCB) U2.P$16(B1)  [also labelled +5V, EQEP1B, EQEP1I, EQEP2A, EQEP2B, EQEP2I]
GND: C31.2 C32.2 C37.2 C50.2 C51.2 C52.2 C53.2 C54.2 C55.2 J2.1 J3.2 J6.1 J7.2 J9.2 J9.3 QEP_A.5 QEP_B.5 R42.2 U3.P$2(GND)
N$18: J12.3
ADCINA0: J3.7
ADCINA1: J3.9
ADCINA2: J3.5
ADCINA3: J7.7
ADCINA4: J7.9
ADCINA5: J7.5
ADCINA6: J1.2
ADCINA7: J3.3
ADCINB0: J3.8
ADCINB1: J3.4
ADCINB2: J3.6
ADCINB3: J7.8
ADCINB4: J7.4
ADCINB5: J7.6
ADCINB6: J1.6
ADCINB7: J7.3
CANH: J12.1 R34.2 U3.P$7(CANH)
CANL: J12.2 R34.1 U3.P$6(CANL)
DAC1: J4.9
DAC2: J4.10
DAC3: J8.9
DAC4: J8.10
GPIO0: J4.1
GPIO1: J4.2
GPIO2: J4.3
GPIO3: J4.4
GPIO4: J4.5
GPIO5: J4.6
GPIO6: J8.1
GPIO7: J8.2
GPIO8: J8.3
GPIO9: J8.4
GPIO10: J8.5
GPIO11: J8.6
GPIO12: J1.5
GPIO13: J4.7
GPIO14: J5.7
GPIO16: J2.6
GPIO17: J2.7
GPIO18: J1.7
GPIO19: J2.2
GPIO20: J5.5 U2.P$1(A1)
GPIO21: J5.8 U2.P$3(A2)
GPIO22: J1.8
GPIO23: J5.9 U2.P$4(A3)
GPIO24: J6.6
GPIO25: J6.7
GPIO26: J6.3
GPIO27: J6.2
GPIO30: R44.2
GPIO31: R43.2
GPIO32: J1.10
GPIO33: J1.9
GPIO44: J2.3
GPIO50: J2.8
GPIO51: J2.9
GPIO52: J6.8
GPIO53: J6.9
GPIO54: J5.10 U2.P$5(A4)
GPIO55: J2.10 U2.P$6(A5)
GPIO56: J6.10 U2.P$7(A6)
J1.3: J1.3
J1.4: J1.4
J7.3: J5.3
J7.4: J5.4
RESET#: J2.5 J6.5
NetJ5_1: J5.1 JP4.1
NetJ7_1: J7.1 JP5.1
NetR2_2: R2.2 U2.P$8(OE)
NetR35_1: R35.1 U3.P$5(EN)
NetR42_1: R42.1 U3.P$8(RS)
NetR43_1: R43.1 U3.P$1(D)
NetR44_1: R44.1 U3.P$4(R)

Not connected (* = marked no-connect by the designer): J2 4; J3 10; J4 8; J5 2 6; J6 4; J7 10; J8 7 8; U2 P$9(GND)

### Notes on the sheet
- (near J5) PWR
- (near J5) ANA
- (near J5) FAULTn
- (near J5) 41
- (near J5) 42
- (near J5) 43
- (near J7) PWR
- (near J7) GND
- (near J7) Vdc
- 61
- 62
- (near J7) 63
- (near J5) 2SPI_CLK
- (near J5) OCTWn
- (near J5) 44
- (near J5) 45
- (near J5) 46
- (near J5) 47
- (near J5) 48
- (near J7) V_A2
- (near J7) V_B2
- (near J7) V_C2
- (near J7) I_A2
- (near J7) I_B2
- (near J7) 64
- (near J7) 65
- (near J7) 66
- (near J7) 67
- (near J7) 68
- (near J5) SCL
- (near J5) SDA
- (near J5) 49
- (near J5) 50
- (near J7) I_C2
- (near J7) 69
- (near J7) 70
- 2PWM_AH
- 2PWM_AL
- 2PWM_BH
- 2PWM_BL
- (near J8) 77
- (near J8) 78
- (near J8) 79
- (near J8) 80
- (near J6) 2SPI_CS
- GND
- GPIO
- (near J6) 57
- (near J6) 58
- (near J6) 59
- (near J6) 60
- 2PWM_CH
- 2PWM_CL
- PWM_DAC
- (near J8) 72
- (near J8) 73
- (near J8) 74
- (near J8) 75
- (near J8) 76
- RESET
- (near J6) 2SPI_SI
- (near J6) 2SPI_SO
- (near J6) 2EN_GATE
- (near J6) 2DC_CAL
- (near J6) 52
- (near J6) 53
- (near J6) 54
- (near J6) 55
- (near J6) 56
- (near J8) 71
- (near J6) 51
- (near J1) FAULTn
- (near J1) OCTWn
- (near J1) PWR
- (near J1) ANA
- (near J1) GPIO
- (near J1) 1
- (near J1) 2
- (near J1) 3
- (near J1) 4
- (near J1) 5
- (near J3) Vdc
- (near J3) V_A1
- (near J3) V_B1
- (near J3) PWR
- (near J3) GND
- (near J3) 21
- (near J3) 22
- (near J3) 23
- (near J3) 24
- (near J3) 25
- (near J1) 1SPI_CLK
- (near J1) 6
- (near J1) 7
- (near J1) 8
- (near J1) 9
- (near J1) 10
- (near J3) V_C1
- (near J3) I_A1
- (near J3) I_B1
- (near J3) I_C1
- (near J3) 26
- (near J3) 27
- (near J3) 28
- (near J3) 29
- (near J3) 30
- 1PWM_AH
- 1PWM_AL
- (near J4) 39
- (near J4) 40
- 1SPI_CS
- (near J2) 19
- (near J2) 20
- (near J4) 1PWM_BH
- (near J4) 1PWM_BL
- (near J4) 1PWM_CH
- (near J4) 1PWM_CL
- (near J4) 34
- (near J4) 35
- (near J4) 36
- (near J4) 37
- (near J4) 38
- (near J2) 1SPI_SI
- (near J2) 1SPI_SO
- (near J2) 14
- (near J2) 15
- (near J2) 16
- (near J2) 17
- (near J2) 18
- (near J4) PWM_DAC
- (near J4) 31
- (near J4) 32
- (near J4) 33
- (near J2) 1EN_GATE
- (near J2) 1DC_CAL
- (near J2) 11
- (near J2) 12
- (near J2) 13
- A
- B
- COMPANY:
- Embest
- Roy Yaung
- Drawn
- Checked
- Approved
- I
- (near QEP_A) GND
- (near QEP_A) PWR
- TITLE:
- LAUNCHXL-F28069_B_1400922
- REV:
- Date:
- Document Number:
- 8/26/2016 1:33:35 PM
- CONNECTOR
- Scale: 1/1
- Sheet:
- 5
- 1.1
- Labels drawn without touching a wire or pin: GND

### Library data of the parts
C31 C32 C37 C50-C55 = C-USC0402: CAPACITOR, American symbol
J1-J8 = MA10-1: PIN HEADER
J9 = CON-LSTB_MA03-1: PIN HEADER
J12 = MA03-1: PIN HEADER
JP4 JP5 = JP1ENORM: JUMPER
QEP_A QEP_B = MA05-1: PIN HEADER
R2 R13 R29 R34 R35 R42-R44 R48-R51 = R-US_R0402: RESISTOR, American symbol

## Sheet LAUNCHXL-F28069_B_1400922_5.SchDoc: LAUNCHXL-F28069_B_1400922
size 301 x 237 mm; Date: 8/26/2016 1:33:36 PM; SheetNumber: 6
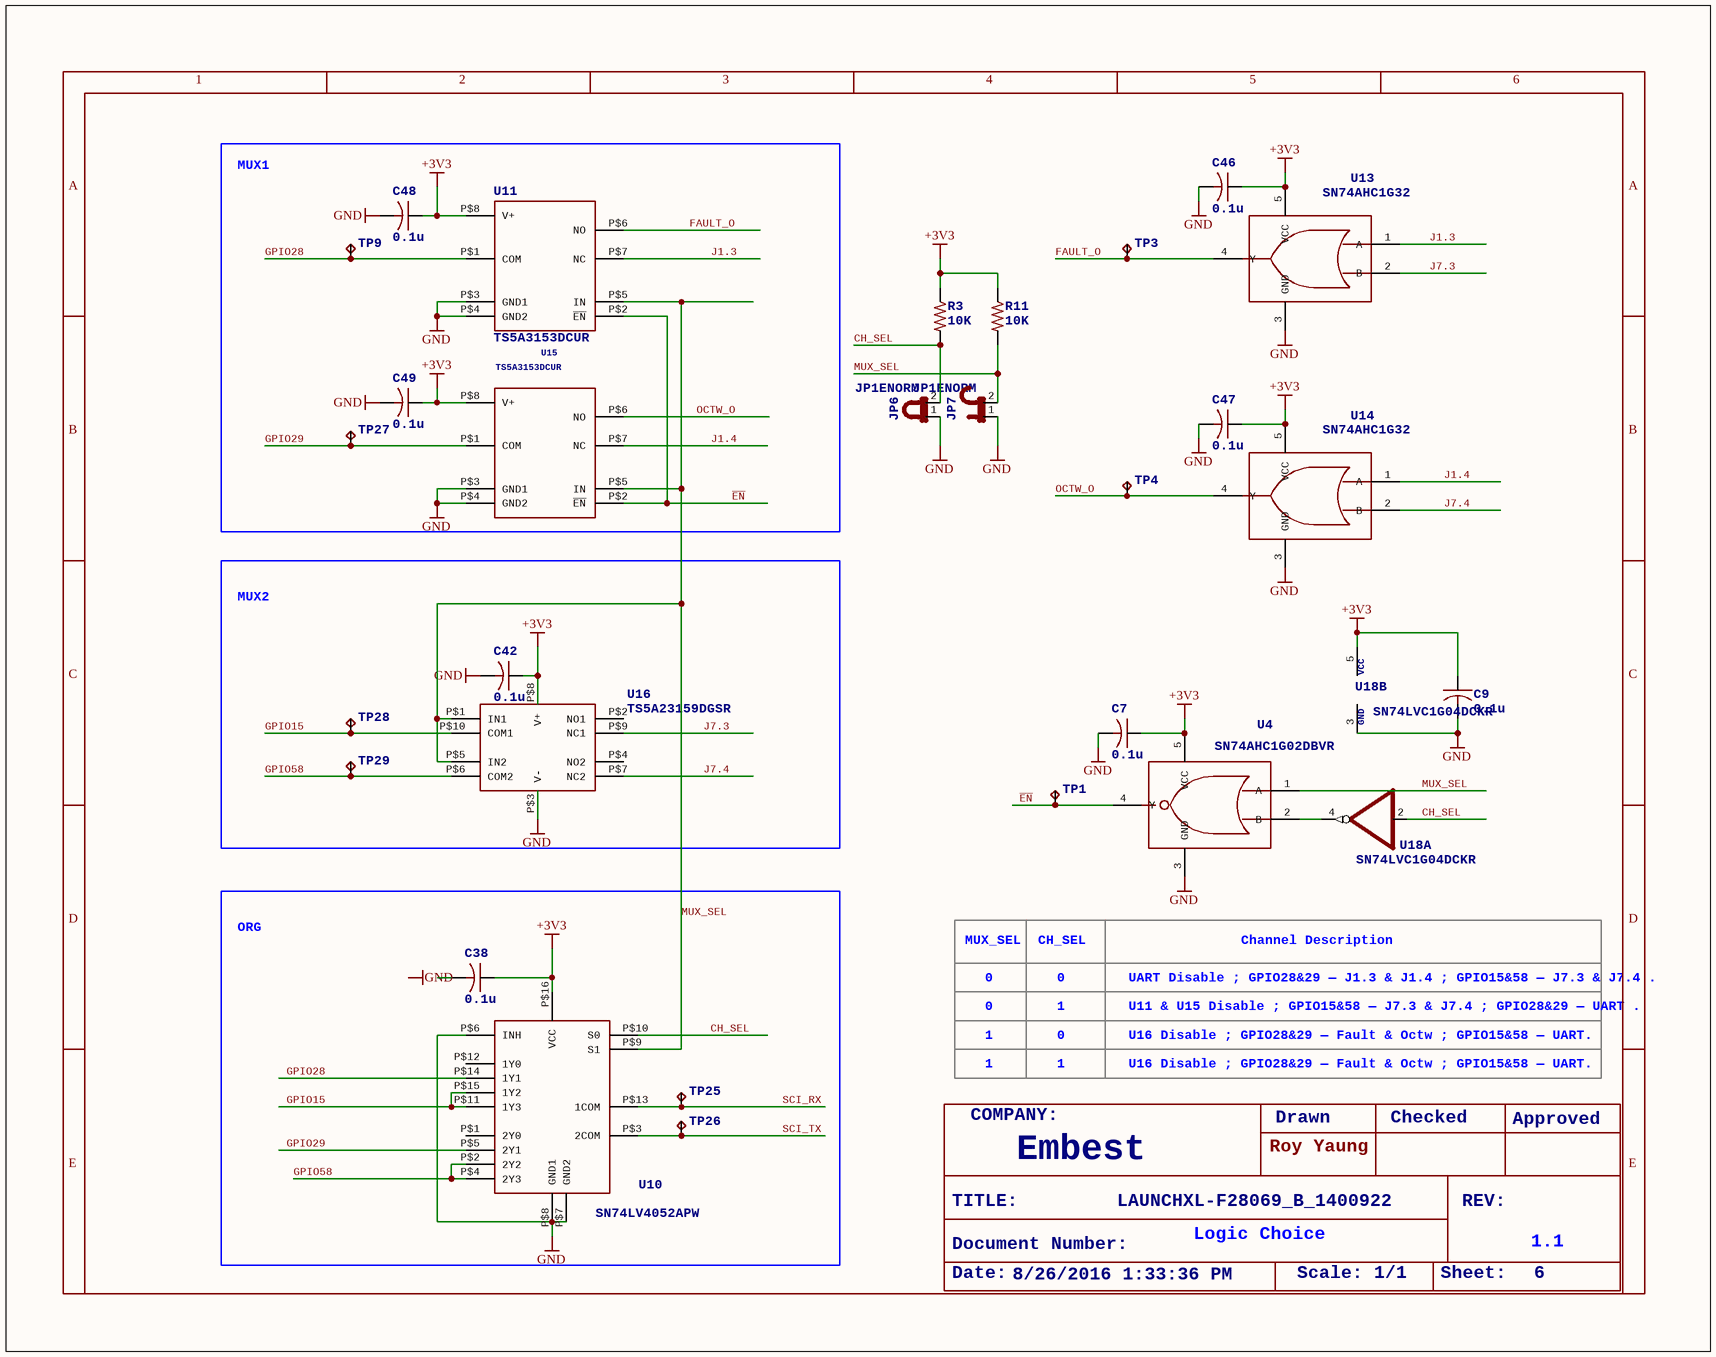
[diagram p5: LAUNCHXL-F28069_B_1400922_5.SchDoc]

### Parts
C7  0.1u  [C0402]
C9  0.1u  [C0402]
C38  0.1u  [C0402]
C42  0.1u  [C0402]
C46  0.1u  [C0402]
C47  0.1u  [C0402]
C48  0.1u  [C0402]
C49  0.1u  [C0402]
JP6  JP1ENORM  [JP1]
JP7  JP1ENORM  [JP1]
R3  10K  [R0402]
R11  10K  [R0402]
TP1  TESTPAD_TPB1,27  [TESTPAD_B1,27]  (value not drawn)
TP3  TESTPAD_TPB1,27  [TESTPAD_B1,27]  (value not drawn)
TP4  TESTPAD_TPB1,27  [TESTPAD_B1,27]  (value not drawn)
TP9  TESTPAD_TPB1,27  [TESTPAD_B1,27]  (value not drawn)
TP25  TESTPAD_TPB1,27  [TESTPAD_B1,27]  (value not drawn)
TP26  TESTPAD_TPB1,27  [TESTPAD_B1,27]  (value not drawn)
TP27  TESTPAD_TPB1,27  [TESTPAD_B1,27]  (value not drawn)
TP28  TESTPAD_TPB1,27  [TESTPAD_B1,27]  (value not drawn)
TP29  TESTPAD_TPB1,27  [TESTPAD_B1,27]  (value not drawn)
U4  SN74AHC1G02DBVR  [SOT23-5-DBV]
U10  SN74LV4052APW  [TSSOP16-PW]
U11  TS5A3153DCUR  [TI-DCU8]
U13  SN74AHC1G32  [SOT23-5-DBV]
U14  SN74AHC1G32  [SOT23-5-DBV]
U15  TS5A3153DCUR  [TI-DCU8]
U16  TS5A23159DGSR  [TI-DGS10]
U18  SN74LVC1G04DCKR  [74XX-LITTLE-DE_SC70-5]  (parts A,B of 2)
U$1  ROY_JUMPER  [ROY_JUMPER]  (value not drawn)
U$2  ROY_JUMPER  [ROY_JUMPER]  (value not drawn)

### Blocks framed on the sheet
MUX1: C48 C49 TP9 TP27 U11 U15
MUX2: C42 TP28 TP29 U16
ORG: C38 TP25 TP26 U10

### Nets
+3V3: C7.1 C9.1 C38.1 C42.1 C46.1 C47.1 C48.1 C49.1 R3.1 R11.1 U4.5(VCC) U10.P$16(VCC) U11.P$8(V+) U13.5(VCC) U14.5(VCC) U15.P$8(V+) U16.P$8(V+) U18.5(VCC)
GND: C7.2 C9.2 C42.2 C46.2 C47.2 C48.2 C49.2 JP6.1 JP7.1 U4.3(GND) U10.P$6(INH) U10.P$7(GND2) U10.P$8(GND1) U11.P$3(GND1) U11.P$4(GND2) U13.3(GND) U14.3(GND) U15.P$3(GND1) U15.P$4(GND2) U16.P$3(V-) U18.3(GND)
CH_SEL: JP6.2 R3.2 U10.P$10(S0) U18.2(I)
~{EN}: TP1.TP U4.4(Y) U11.P$2(~{EN}) U15.P$2(~{EN})
FAULT_O: TP3.TP U11.P$6(NO) U13.4(Y)
GPIO15: TP28.TP U10.P$11(1Y3) U10.P$15(1Y2) U16.P$10(COM1)
GPIO28: TP9.TP U10.P$14(1Y1) U11.P$1(COM)
GPIO29: TP27.TP U10.P$5(2Y1) U15.P$1(COM)
GPIO58: TP29.TP U10.P$2(2Y2) U10.P$4(2Y3) U16.P$6(COM2)
J1.3: U11.P$7(NC) U13.1(A)
J1.4: U14.1(A) U15.P$7(NC)
J7.3: U13.2(B) U16.P$9(NC1)
J7.4: U14.2(B) U16.P$7(NC2)
MUX_SEL: JP7.2 R11.2 U4.1(A) U10.P$9(S1) U11.P$5(IN) U15.P$5(IN) U16.P$1(IN1) U16.P$5(IN2)
OCTW_O: TP4.TP U14.4(Y) U15.P$6(NO)
SCI_RX: TP25.TP U10.P$13(1COM)
SCI_TX: TP26.TP U10.P$3(2COM)
NetU4_2: U4.2(B) U18.4(O)

Not connected (* = marked no-connect by the designer): C38 2; U10 P$1(2Y0) P$12(1Y0); U16 P$2(NO1) P$4(NO2)

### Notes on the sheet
- MUX_SEL
- CH_SEL
- Channel Description
- 0
- 1
- UART Disable ; GPIO28&29 — J1.3 & J1.4 ; GPIO15&58 — J7.3 & J7.4 .
- U11 & U15 Disable ; GPIO15&58 — J7.3 & J7.4 ; GPIO28&29 — UART .
- U16 Disable ; GPIO28&29 — Fault & Octw ; GPIO15&58 — UART.
- COMPANY:
- Embest
- Roy Yaung
- Drawn
- Checked
- Approved
- TITLE:
- LAUNCHXL-F28069_B_1400922
- REV:
- Date:
- Document Number:
- 8/26/2016 1:33:36 PM
- Logic Choice
- Scale: 1/1
- Sheet:
- 1.1
- 6
- Labels drawn without touching a wire or pin: GND

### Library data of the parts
C7 C9 C38 C42 C46-C49 = C-USC0402: CAPACITOR, American symbol
JP6 JP7 = JP1ENORM: JUMPER
R3 R11 = R-US_R0402: RESISTOR, American symbol
TP1 TP3 TP4 TP9 TP25-TP29 = TESTPAD_TPB1,27: Test pad
U4 = SN74AHC1G02
U18 = 74XX-LITTLE-DE_74*1G04DCK: INVERTER Gate

## Sheet LAUNCHXL-F28069_B_1400922_6.SchDoc: LAUNCHXL-F28069_B_1400922
size 301 x 237 mm; Date: 8/26/2016 1:33:37 PM; SheetNumber: 7
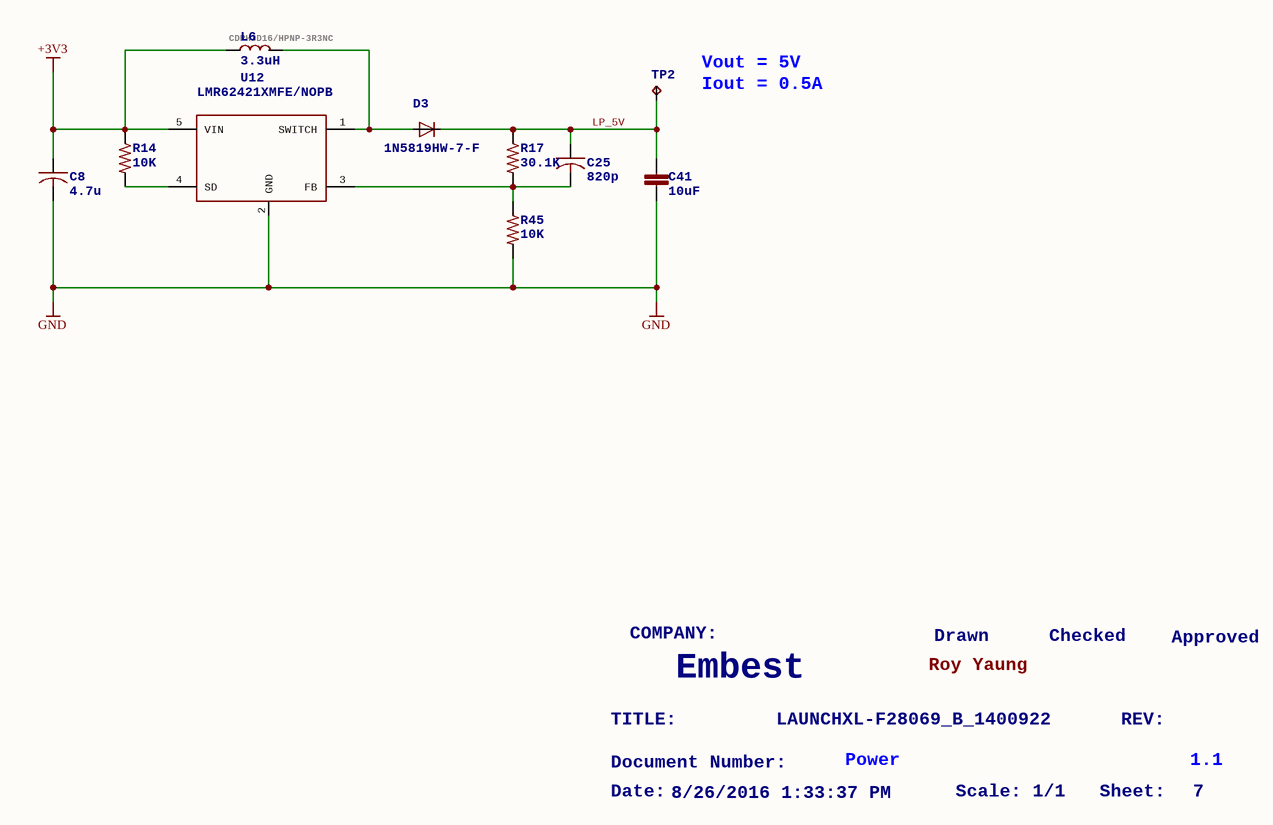
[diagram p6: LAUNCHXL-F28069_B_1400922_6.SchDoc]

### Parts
C8  4.7u  [C0402]
C25  820p  [C0402]
C41  10uF  [SPARKFUN_1210]
D3  1N5819HW-7-F  [SOD123]
L6  3.3uH  [INDUCT-3_7*3_5]
R14  10K  [R0402]
R17  30.1K  [R0402]
R45  10K  [R0402]
TP2  TESTPAD_TPB1,27  [TESTPAD_B1,27]  (value not drawn)
U12  LMR62421XMFE/NOPB  [SOT23-5-DBV]

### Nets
+3V3: C8.1 L6.P$1 R14.1 U12.5(VIN)
GND: C8.2 C41.1 R45.2 U12.2(GND)
LP_5V: C25.1 C41.2 D3.C R17.1 TP2.TP
NetC25_2: C25.2 R17.2 R45.1 U12.3(FB)
NetD3_A: D3.A L6.P$2 U12.1(SWITCH)
NetR14_2: R14.2 U12.4(SD)

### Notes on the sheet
- (near L6) CDRH3D16/HPNP-3R3NC
- (near TP2) Vout = 5V
- (near TP2) Iout = 0.5A
- COMPANY:
- Embest
- Roy Yaung
- Drawn
- Checked
- Approved
- TITLE:
- LAUNCHXL-F28069_B_1400922
- REV:
- Date:
- Document Number:
- 8/26/2016 1:33:37 PM
- Power
- Scale: 1/1
- Sheet:
- 1.1
- 7

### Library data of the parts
C8 C25 = C-USC0402: CAPACITOR, American symbol
C41 = SPARKFUN_CAP1210: as C44 on sheet LAUNCHXL-F28069_B_1400922_1
D3 = 1N4148: DIODE   high speed (Philips)
L6 = VLF4012A
R14 R17 R45 = R-US_R0402: RESISTOR, American symbol
TP2 = TESTPAD_TPB1,27: Test pad

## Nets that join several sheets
+3V3: LAUNCHXL-F28069_B_1400922_1 (8 pins), LAUNCHXL-F28069_B_1400922_2 (9 pins), LAUNCHXL-F28069_B_1400922_3 (C24.1 R38.2 R39.2 U9.5), LAUNCHXL-F28069_B_1400922_4 (9 pins), LAUNCHXL-F28069_B_1400922_5 (18 pins), LAUNCHXL-F28069_B_1400922_6 (C8.1 L6.P$1 R14.1 U12.5)
EQEP1A: LAUNCHXL-F28069_B_1400922_1 (JP3.2 TP10.TP), LAUNCHXL-F28069_B_1400922_4 (36 pins)
GND: LAUNCHXL-F28069_B_1400922_1 (6 pins), LAUNCHXL-F28069_B_1400922_2 (39 pins), LAUNCHXL-F28069_B_1400922_3 (6 pins), LAUNCHXL-F28069_B_1400922_4 (19 pins), LAUNCHXL-F28069_B_1400922_5 (21 pins), LAUNCHXL-F28069_B_1400922_6 (C8.2 C41.1 R45.2 U12.2)
ADCINA0: LAUNCHXL-F28069_B_1400922_2 (U1.23), LAUNCHXL-F28069_B_1400922_4 (J3.7)
ADCINA1: LAUNCHXL-F28069_B_1400922_2 (U1.22), LAUNCHXL-F28069_B_1400922_4 (J3.9)
ADCINA2: LAUNCHXL-F28069_B_1400922_2 (U1.21), LAUNCHXL-F28069_B_1400922_4 (J3.5)
ADCINA3: LAUNCHXL-F28069_B_1400922_2 (U1.20), LAUNCHXL-F28069_B_1400922_4 (J7.7)
ADCINA4: LAUNCHXL-F28069_B_1400922_2 (U1.19), LAUNCHXL-F28069_B_1400922_4 (J7.9)
ADCINA5: LAUNCHXL-F28069_B_1400922_2 (U1.18), LAUNCHXL-F28069_B_1400922_4 (J7.5)
ADCINA6: LAUNCHXL-F28069_B_1400922_2 (U1.17), LAUNCHXL-F28069_B_1400922_4 (J1.2)
ADCINA7: LAUNCHXL-F28069_B_1400922_2 (U1.16), LAUNCHXL-F28069_B_1400922_4 (J3.3)
ADCINB0: LAUNCHXL-F28069_B_1400922_2 (U1.28), LAUNCHXL-F28069_B_1400922_4 (J3.8)
ADCINB1: LAUNCHXL-F28069_B_1400922_2 (U1.29), LAUNCHXL-F28069_B_1400922_4 (J3.4)
ADCINB2: LAUNCHXL-F28069_B_1400922_2 (U1.30), LAUNCHXL-F28069_B_1400922_4 (J3.6)
ADCINB3: LAUNCHXL-F28069_B_1400922_2 (U1.31), LAUNCHXL-F28069_B_1400922_4 (J7.8)
ADCINB4: LAUNCHXL-F28069_B_1400922_2 (U1.32), LAUNCHXL-F28069_B_1400922_4 (J7.4)
ADCINB5: LAUNCHXL-F28069_B_1400922_2 (U1.33), LAUNCHXL-F28069_B_1400922_4 (J7.6)
ADCINB6: LAUNCHXL-F28069_B_1400922_2 (U1.34), LAUNCHXL-F28069_B_1400922_4 (J1.6)
ADCINB7: LAUNCHXL-F28069_B_1400922_2 (U1.35), LAUNCHXL-F28069_B_1400922_4 (J7.3)
DAC1: LAUNCHXL-F28069_B_1400922_3 (C36.1 R36.2 TP8.TP), LAUNCHXL-F28069_B_1400922_4 (J4.9)
DAC2: LAUNCHXL-F28069_B_1400922_3 (C33.1 R37.2 TP7.TP), LAUNCHXL-F28069_B_1400922_4 (J4.10)
DAC3: LAUNCHXL-F28069_B_1400922_3 (C34.1 R40.2 TP6.TP), LAUNCHXL-F28069_B_1400922_4 (J8.9)
DAC4: LAUNCHXL-F28069_B_1400922_3 (C35.1 R41.2 TP5.TP), LAUNCHXL-F28069_B_1400922_4 (J8.10)
GPIO0: LAUNCHXL-F28069_B_1400922_3 (U1.87), LAUNCHXL-F28069_B_1400922_4 (J4.1)
GPIO1: LAUNCHXL-F28069_B_1400922_3 (U1.86), LAUNCHXL-F28069_B_1400922_4 (J4.2)
GPIO2: LAUNCHXL-F28069_B_1400922_3 (U1.84), LAUNCHXL-F28069_B_1400922_4 (J4.3)
GPIO3: LAUNCHXL-F28069_B_1400922_3 (U1.83), LAUNCHXL-F28069_B_1400922_4 (J4.4)
GPIO4: LAUNCHXL-F28069_B_1400922_3 (U1.9), LAUNCHXL-F28069_B_1400922_4 (J4.5)
GPIO5: LAUNCHXL-F28069_B_1400922_3 (U1.10), LAUNCHXL-F28069_B_1400922_4 (J4.6)
GPIO6: LAUNCHXL-F28069_B_1400922_3 (U1.58), LAUNCHXL-F28069_B_1400922_4 (J8.1)
GPIO7: LAUNCHXL-F28069_B_1400922_3 (U1.57), LAUNCHXL-F28069_B_1400922_4 (J8.2)
GPIO8: LAUNCHXL-F28069_B_1400922_3 (U1.54), LAUNCHXL-F28069_B_1400922_4 (J8.3)
GPIO9: LAUNCHXL-F28069_B_1400922_3 (U1.49), LAUNCHXL-F28069_B_1400922_4 (J8.4)
GPIO10: LAUNCHXL-F28069_B_1400922_3 (U1.74), LAUNCHXL-F28069_B_1400922_4 (J8.5)
GPIO11: LAUNCHXL-F28069_B_1400922_3 (U1.73), LAUNCHXL-F28069_B_1400922_4 (J8.6)
GPIO12: LAUNCHXL-F28069_B_1400922_3 (U1.44), LAUNCHXL-F28069_B_1400922_4 (J1.5)
GPIO13: LAUNCHXL-F28069_B_1400922_3 (U1.95), LAUNCHXL-F28069_B_1400922_4 (J4.7)
GPIO14: LAUNCHXL-F28069_B_1400922_3 (U1.96), LAUNCHXL-F28069_B_1400922_4 (J5.7)
GPIO15: LAUNCHXL-F28069_B_1400922_3 (U1.88), LAUNCHXL-F28069_B_1400922_5 (TP28.TP U10.P$11 U10.P$15 U16.P$10)
GPIO16: LAUNCHXL-F28069_B_1400922_3 (U1.55), LAUNCHXL-F28069_B_1400922_4 (J2.6)
GPIO17: LAUNCHXL-F28069_B_1400922_3 (U1.52), LAUNCHXL-F28069_B_1400922_4 (J2.7)
GPIO18: LAUNCHXL-F28069_B_1400922_2 (U1.51), LAUNCHXL-F28069_B_1400922_4 (J1.7)
GPIO19: LAUNCHXL-F28069_B_1400922_2 (U1.64), LAUNCHXL-F28069_B_1400922_4 (J2.2)
GPIO20: LAUNCHXL-F28069_B_1400922_3 (U1.6), LAUNCHXL-F28069_B_1400922_4 (J5.5 U2.P$1)
GPIO21: LAUNCHXL-F28069_B_1400922_3 (U1.7), LAUNCHXL-F28069_B_1400922_4 (J5.8 U2.P$3)
GPIO22: LAUNCHXL-F28069_B_1400922_3 (U1.98), LAUNCHXL-F28069_B_1400922_4 (J1.8)
GPIO23: LAUNCHXL-F28069_B_1400922_3 (U1.2), LAUNCHXL-F28069_B_1400922_4 (J5.9 U2.P$4)
GPIO24: LAUNCHXL-F28069_B_1400922_3 (U1.97), LAUNCHXL-F28069_B_1400922_4 (J6.6)
GPIO25: LAUNCHXL-F28069_B_1400922_3 (U1.39), LAUNCHXL-F28069_B_1400922_4 (J6.7)
GPIO26: LAUNCHXL-F28069_B_1400922_3 (U1.78), LAUNCHXL-F28069_B_1400922_4 (J6.3)
GPIO27: LAUNCHXL-F28069_B_1400922_3 (U1.77), LAUNCHXL-F28069_B_1400922_4 (J6.2)
GPIO28: LAUNCHXL-F28069_B_1400922_3 (U1.50), LAUNCHXL-F28069_B_1400922_5 (TP9.TP U10.P$14 U11.P$1)
GPIO29: LAUNCHXL-F28069_B_1400922_3 (U1.43), LAUNCHXL-F28069_B_1400922_5 (TP27.TP U10.P$5 U15.P$1)
GPIO30: LAUNCHXL-F28069_B_1400922_3 (U1.41), LAUNCHXL-F28069_B_1400922_4 (R44.2)
GPIO31: LAUNCHXL-F28069_B_1400922_3 (U1.40), LAUNCHXL-F28069_B_1400922_4 (R43.2)
GPIO32: LAUNCHXL-F28069_B_1400922_3 (U1.99), LAUNCHXL-F28069_B_1400922_4 (J1.10)
GPIO33: LAUNCHXL-F28069_B_1400922_3 (U1.100), LAUNCHXL-F28069_B_1400922_4 (J1.9)
GPIO34: LAUNCHXL-F28069_B_1400922_2 (R8.2 S1.1), LAUNCHXL-F28069_B_1400922_3 (U1.68 U9.1)
GPIO44: LAUNCHXL-F28069_B_1400922_3 (U1.56), LAUNCHXL-F28069_B_1400922_4 (J2.3)
GPIO50: LAUNCHXL-F28069_B_1400922_3 (U1.42), LAUNCHXL-F28069_B_1400922_4 (J2.8)
GPIO51: LAUNCHXL-F28069_B_1400922_3 (U1.48), LAUNCHXL-F28069_B_1400922_4 (J2.9)
GPIO52: LAUNCHXL-F28069_B_1400922_3 (U1.53), LAUNCHXL-F28069_B_1400922_4 (J6.8)
GPIO53: LAUNCHXL-F28069_B_1400922_3 (U1.65), LAUNCHXL-F28069_B_1400922_4 (J6.9)
GPIO54: LAUNCHXL-F28069_B_1400922_3 (U1.69), LAUNCHXL-F28069_B_1400922_4 (J5.10 U2.P$5)
GPIO55: LAUNCHXL-F28069_B_1400922_3 (U1.75), LAUNCHXL-F28069_B_1400922_4 (J2.10 U2.P$6)
GPIO56: LAUNCHXL-F28069_B_1400922_3 (U1.85), LAUNCHXL-F28069_B_1400922_4 (J6.10 U2.P$7)
GPIO58: LAUNCHXL-F28069_B_1400922_3 (U1.94), LAUNCHXL-F28069_B_1400922_5 (TP29.TP U10.P$2 U10.P$4 U16.P$6)
J1.3: LAUNCHXL-F28069_B_1400922_4 (J1.3), LAUNCHXL-F28069_B_1400922_5 (U11.P$7 U13.1)
J1.4: LAUNCHXL-F28069_B_1400922_4 (J1.4), LAUNCHXL-F28069_B_1400922_5 (U14.1 U15.P$7)
J7.3: LAUNCHXL-F28069_B_1400922_4 (J5.3), LAUNCHXL-F28069_B_1400922_5 (U13.2 U16.P$9)
J7.4: LAUNCHXL-F28069_B_1400922_4 (J5.4), LAUNCHXL-F28069_B_1400922_5 (U14.2 U16.P$7)
JTAG_TRST: LAUNCHXL-F28069_B_1400922_1 (R28.2 U7.5), LAUNCHXL-F28069_B_1400922_2 (S1.4)
LP_5V: LAUNCHXL-F28069_B_1400922_1 (JP3.1), LAUNCHXL-F28069_B_1400922_6 (5 pins)
RESET#: LAUNCHXL-F28069_B_1400922_2 (6 pins), LAUNCHXL-F28069_B_1400922_4 (J2.5 J6.5)
SCI_RX: LAUNCHXL-F28069_B_1400922_1 (R16.2 U5.11), LAUNCHXL-F28069_B_1400922_5 (TP25.TP U10.P$13)
SCI_TX: LAUNCHXL-F28069_B_1400922_1 (R30.2 U7.4), LAUNCHXL-F28069_B_1400922_5 (TP26.TP U10.P$3)
TCK: LAUNCHXL-F28069_B_1400922_1 (R20.2 U5.14), LAUNCHXL-F28069_B_1400922_2 (U1.67)
TDI: LAUNCHXL-F28069_B_1400922_1 (R19.2 U5.13), LAUNCHXL-F28069_B_1400922_2 (U1.71)
TDO: LAUNCHXL-F28069_B_1400922_1 (R32.2 U7.3), LAUNCHXL-F28069_B_1400922_2 (R9.2 S1.2 U1.70)
TMS: LAUNCHXL-F28069_B_1400922_1 (R18.2 U5.12), LAUNCHXL-F28069_B_1400922_2 (U1.72)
